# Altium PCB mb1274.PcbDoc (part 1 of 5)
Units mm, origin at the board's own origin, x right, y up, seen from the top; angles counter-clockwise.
Board outline 70 x 105 mm, 4 copper layers (Top Layer, Mid-Layer 1, Mid-Layer 2, Bottom Layer), stack 1.58 mm thick; 329 components, 271 nets, 1213 pads, 779 vias.
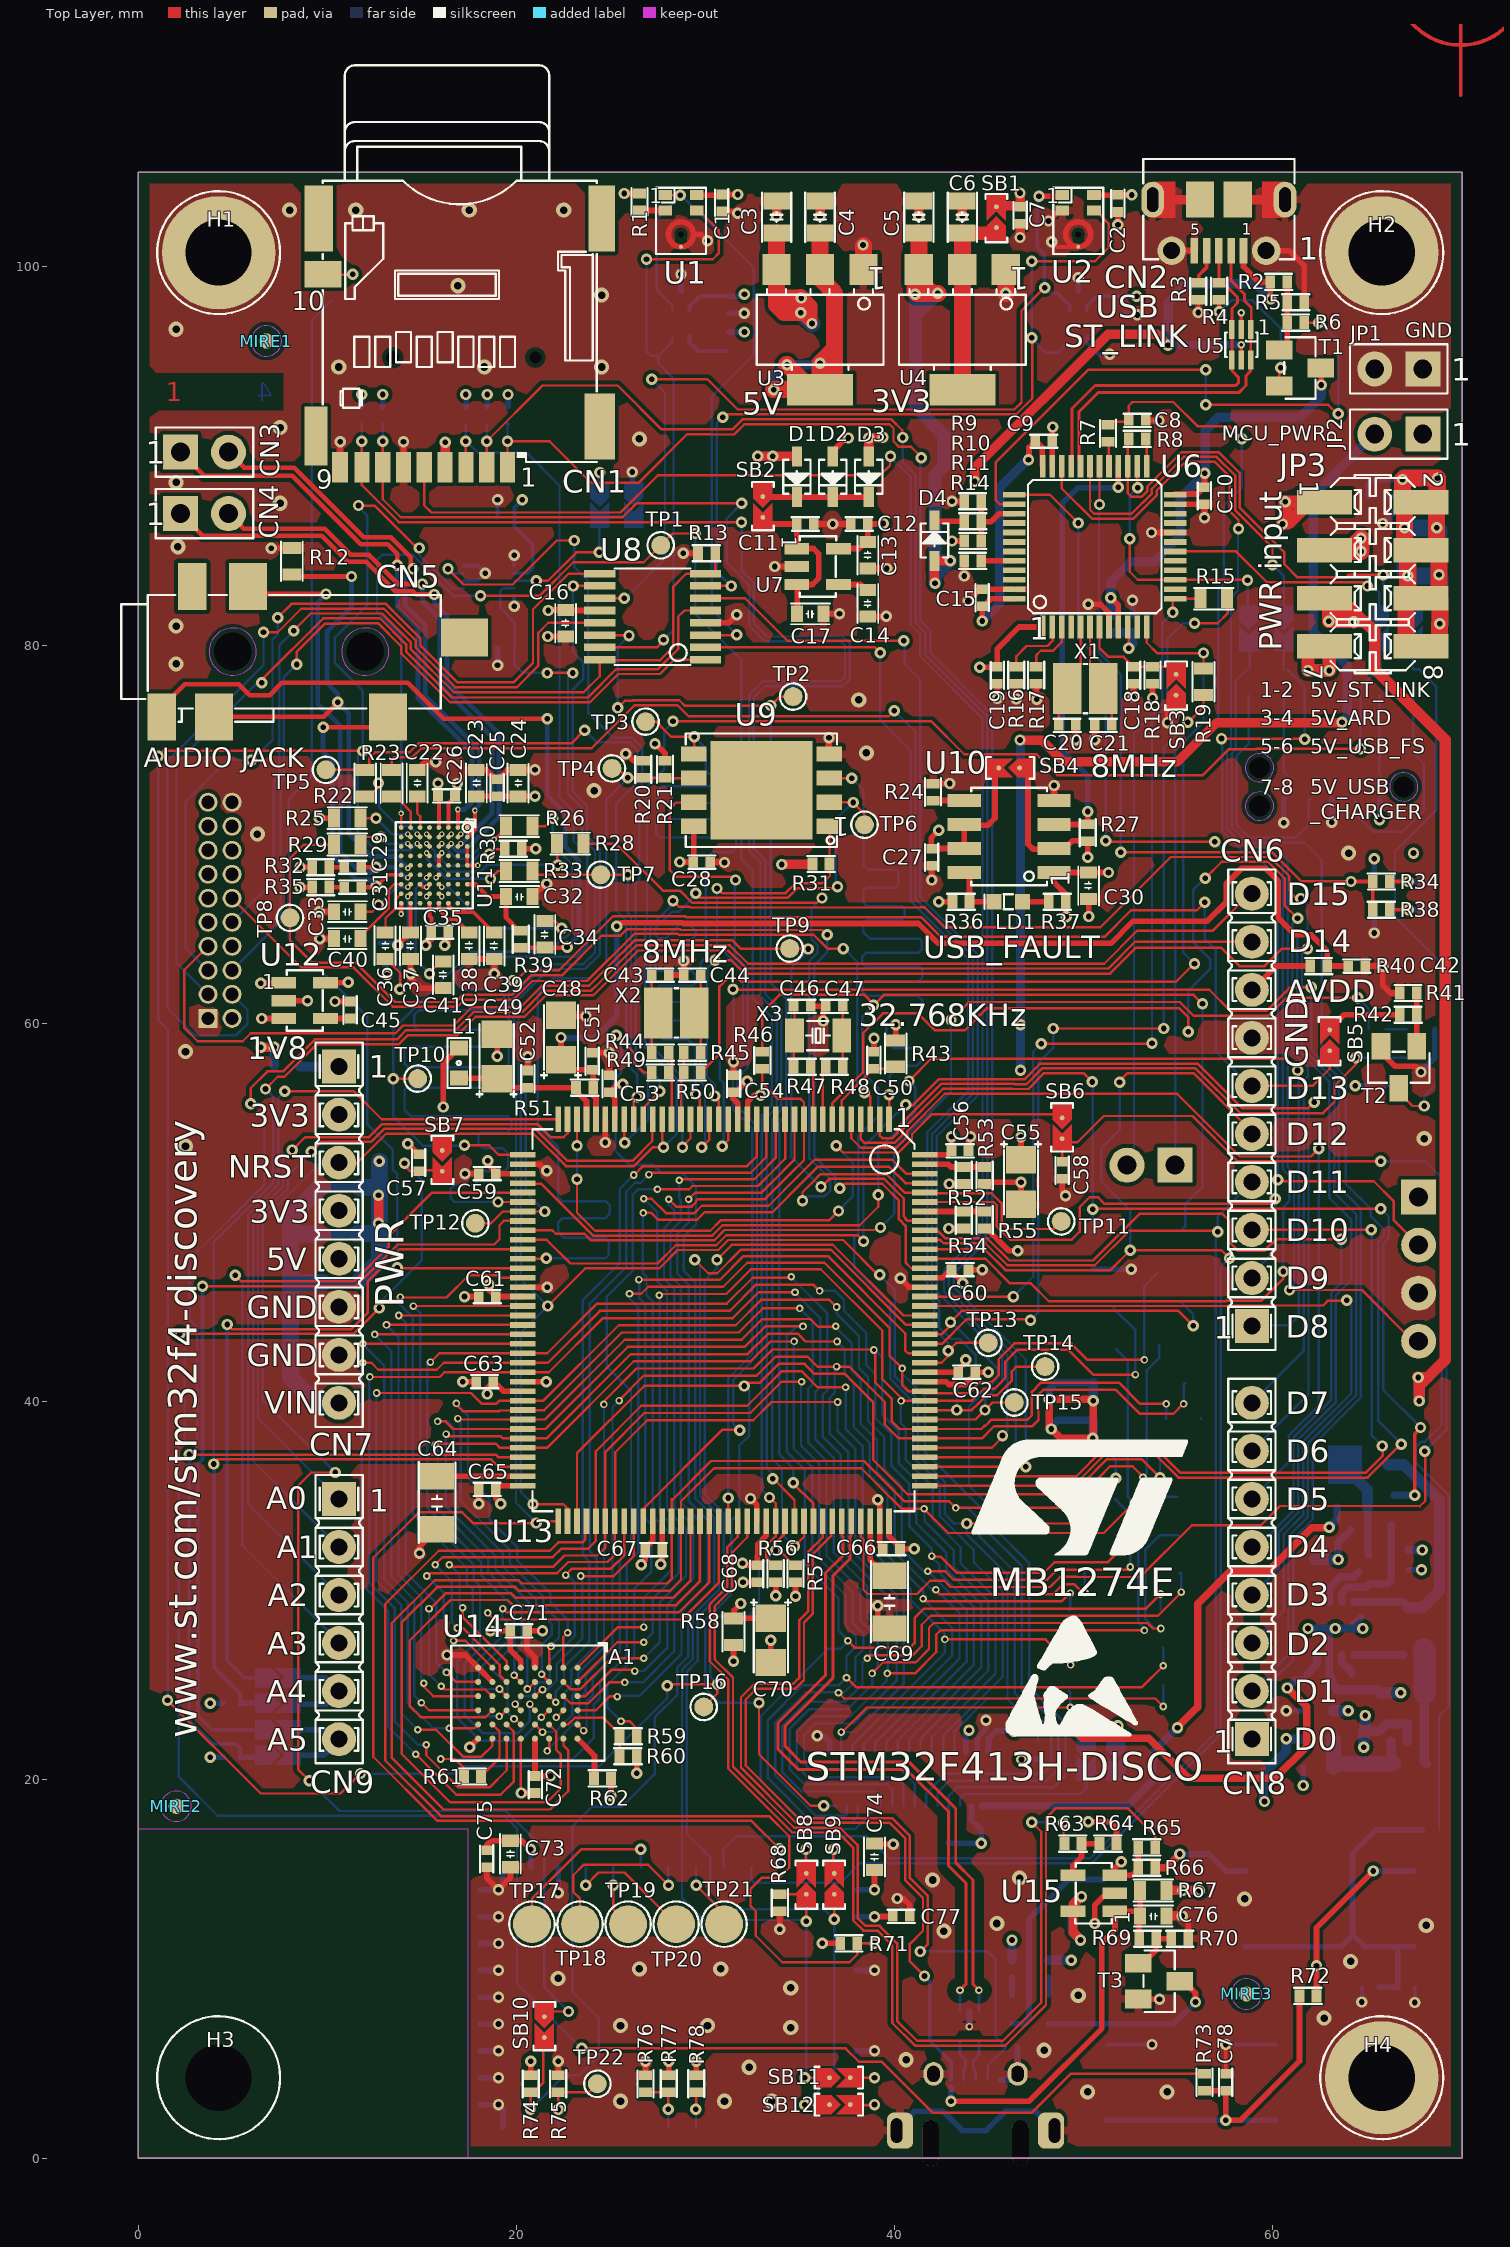
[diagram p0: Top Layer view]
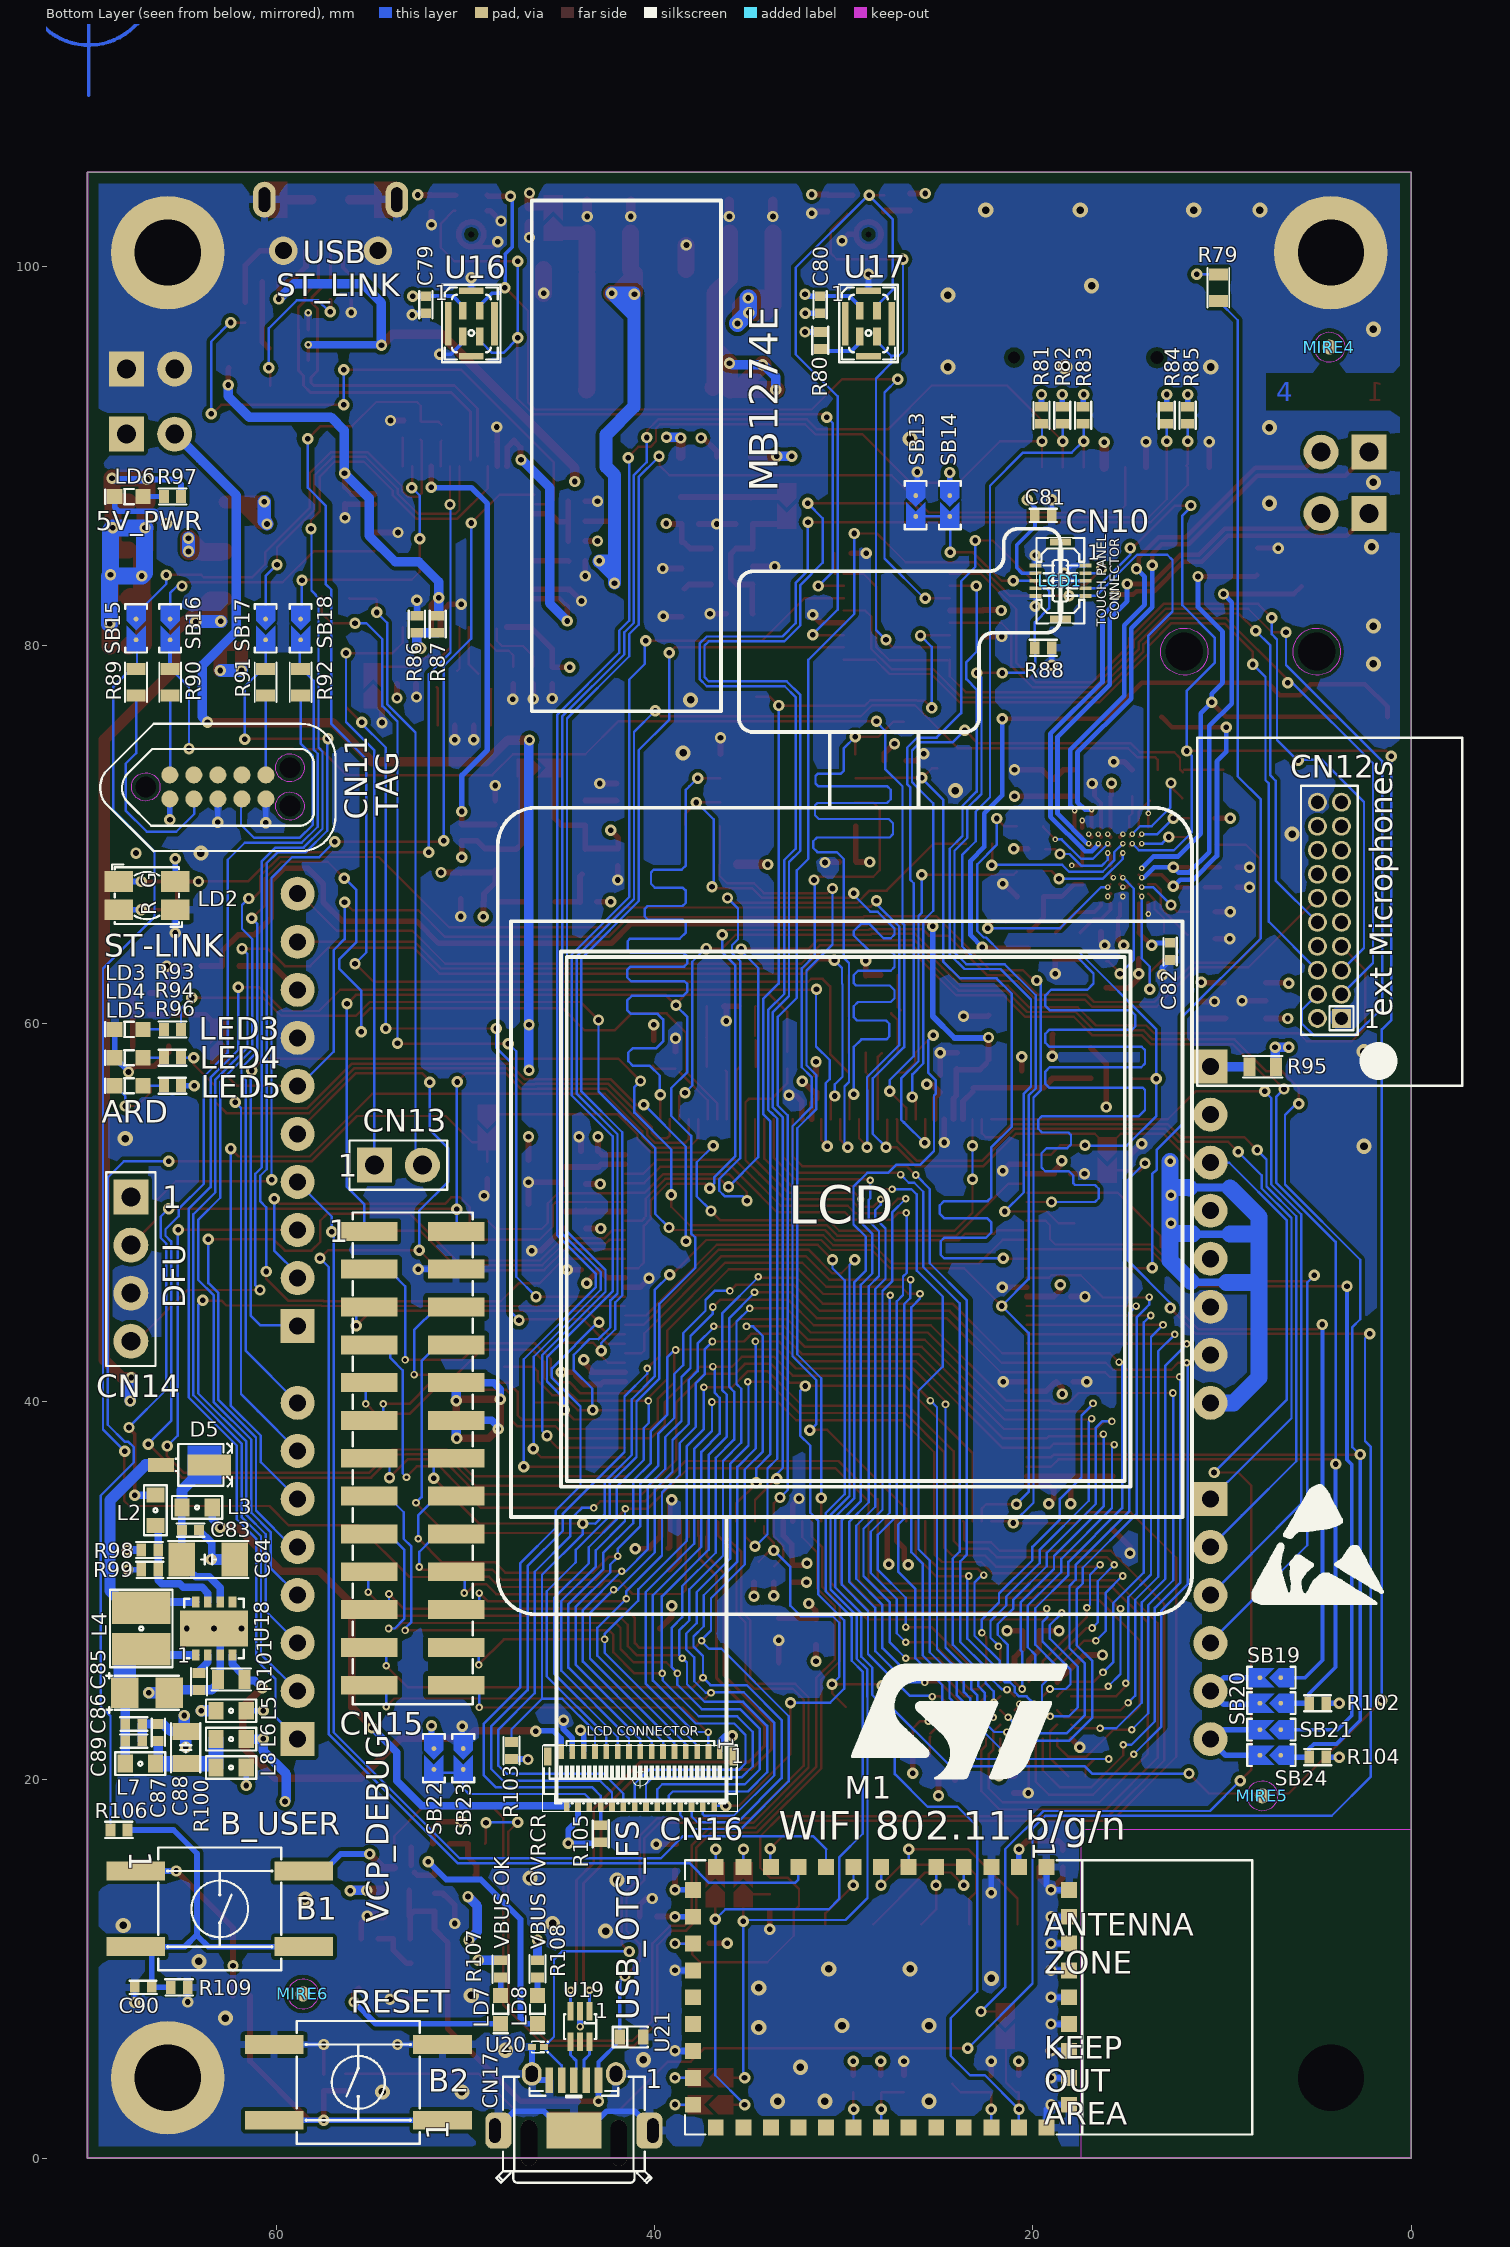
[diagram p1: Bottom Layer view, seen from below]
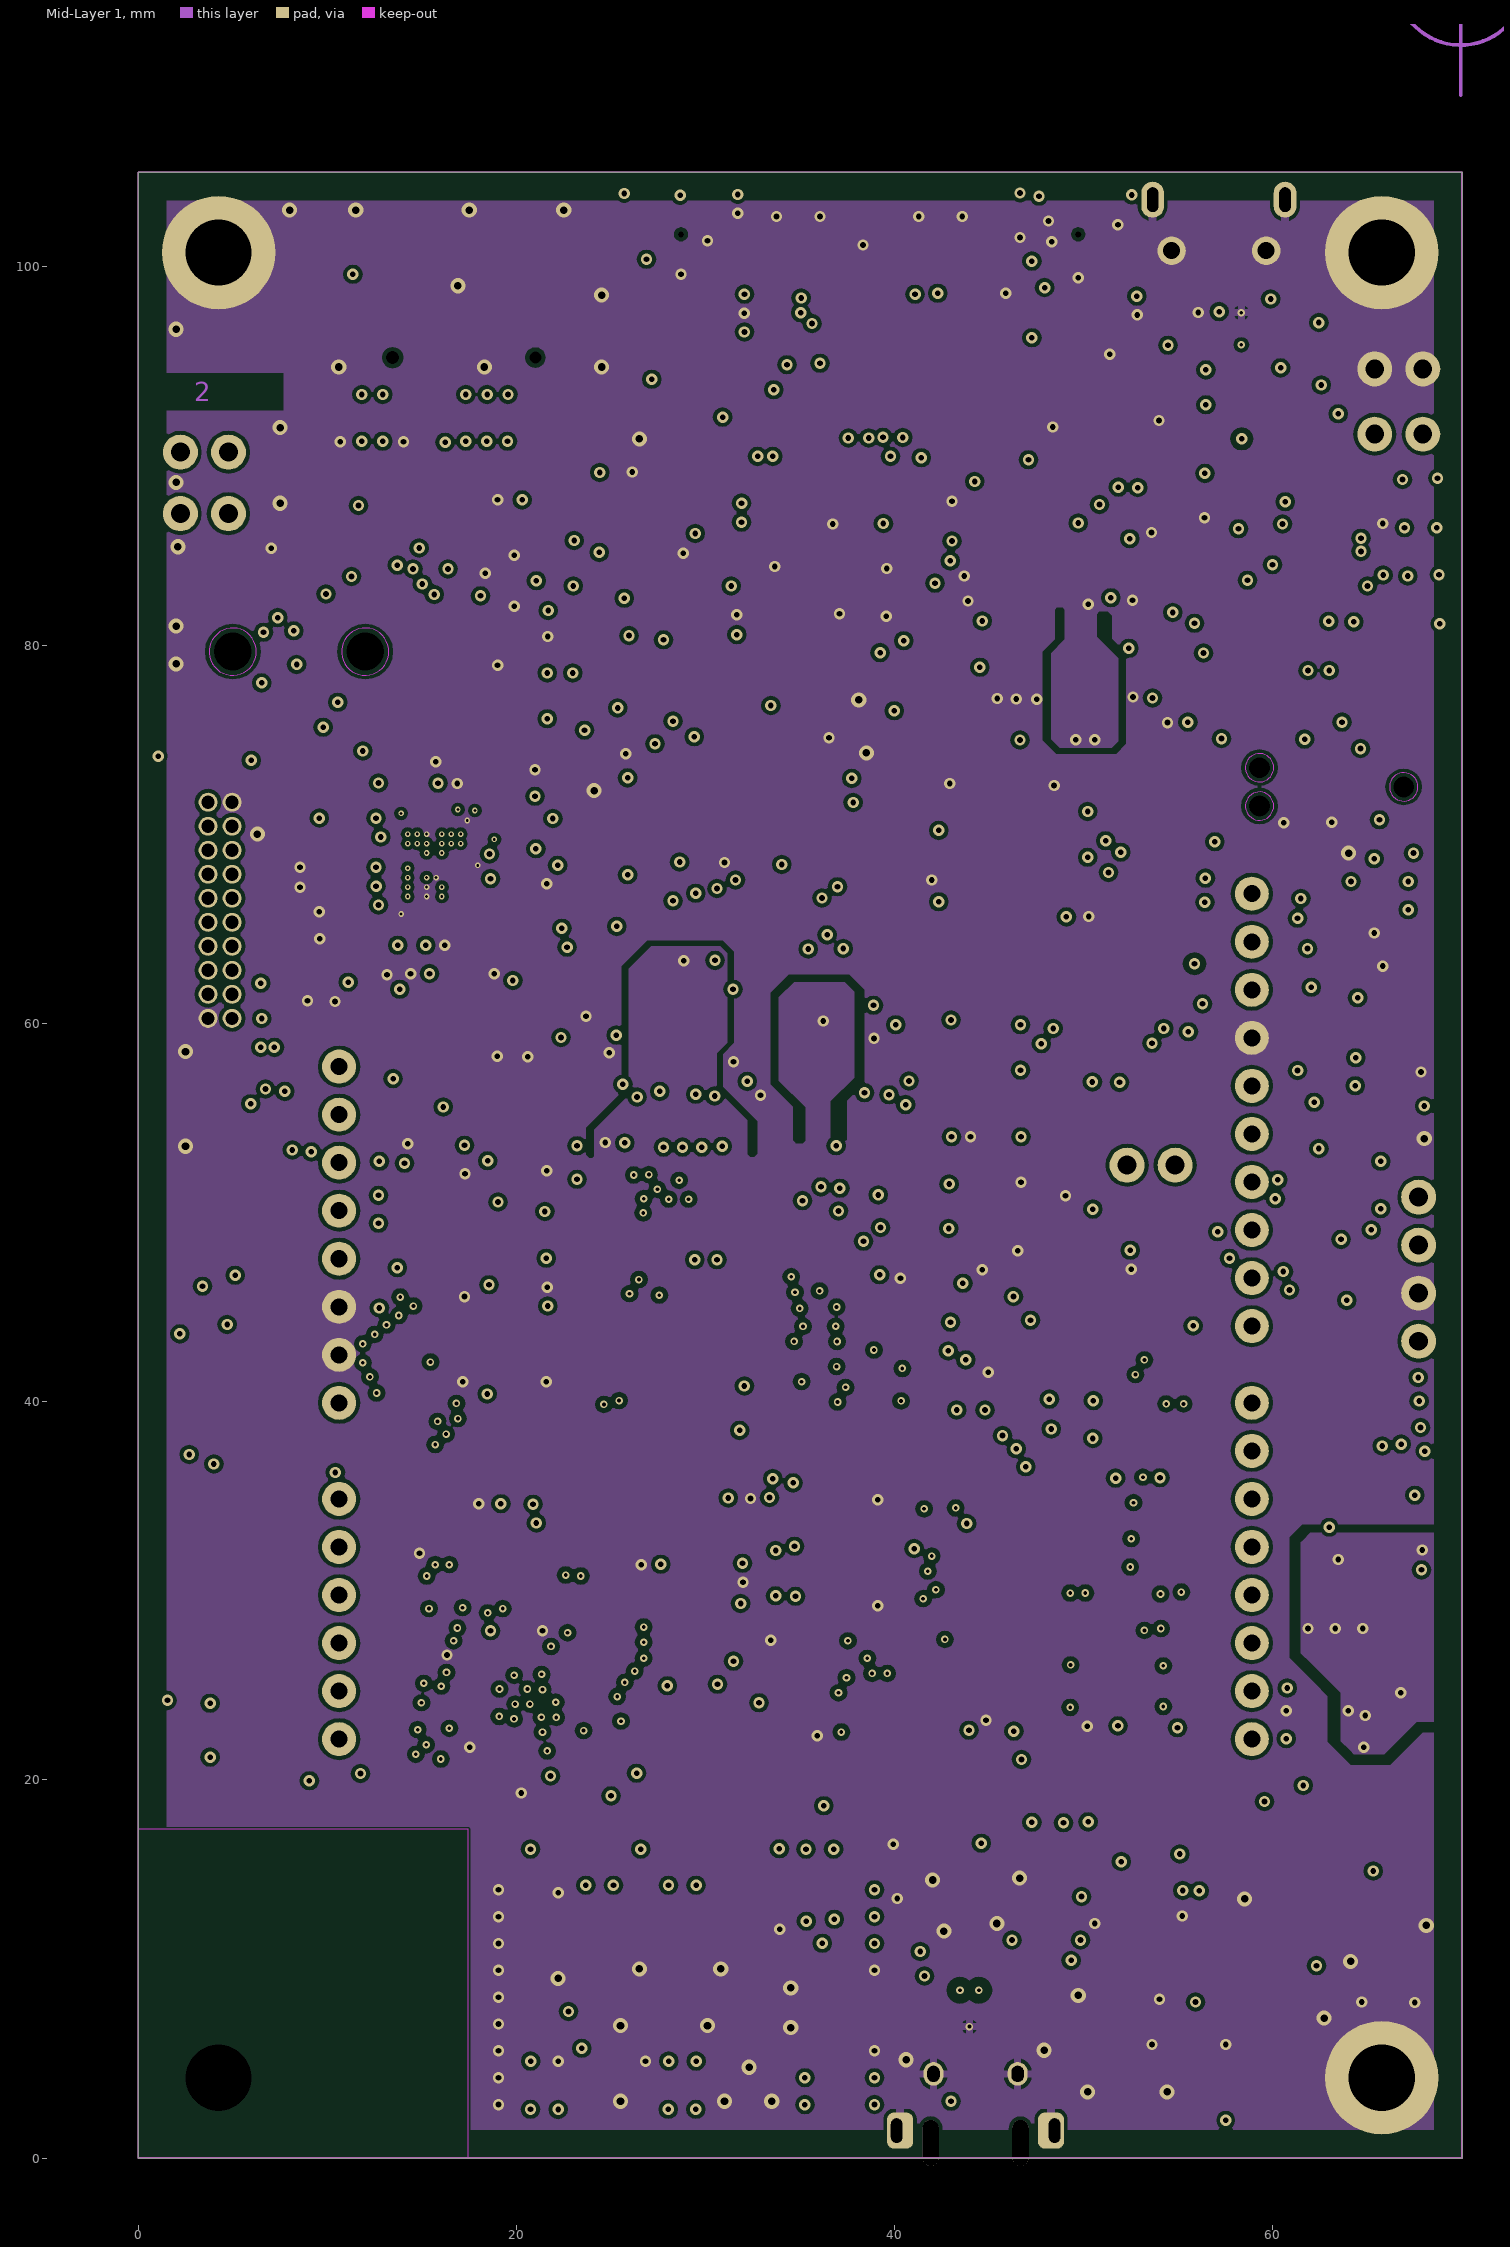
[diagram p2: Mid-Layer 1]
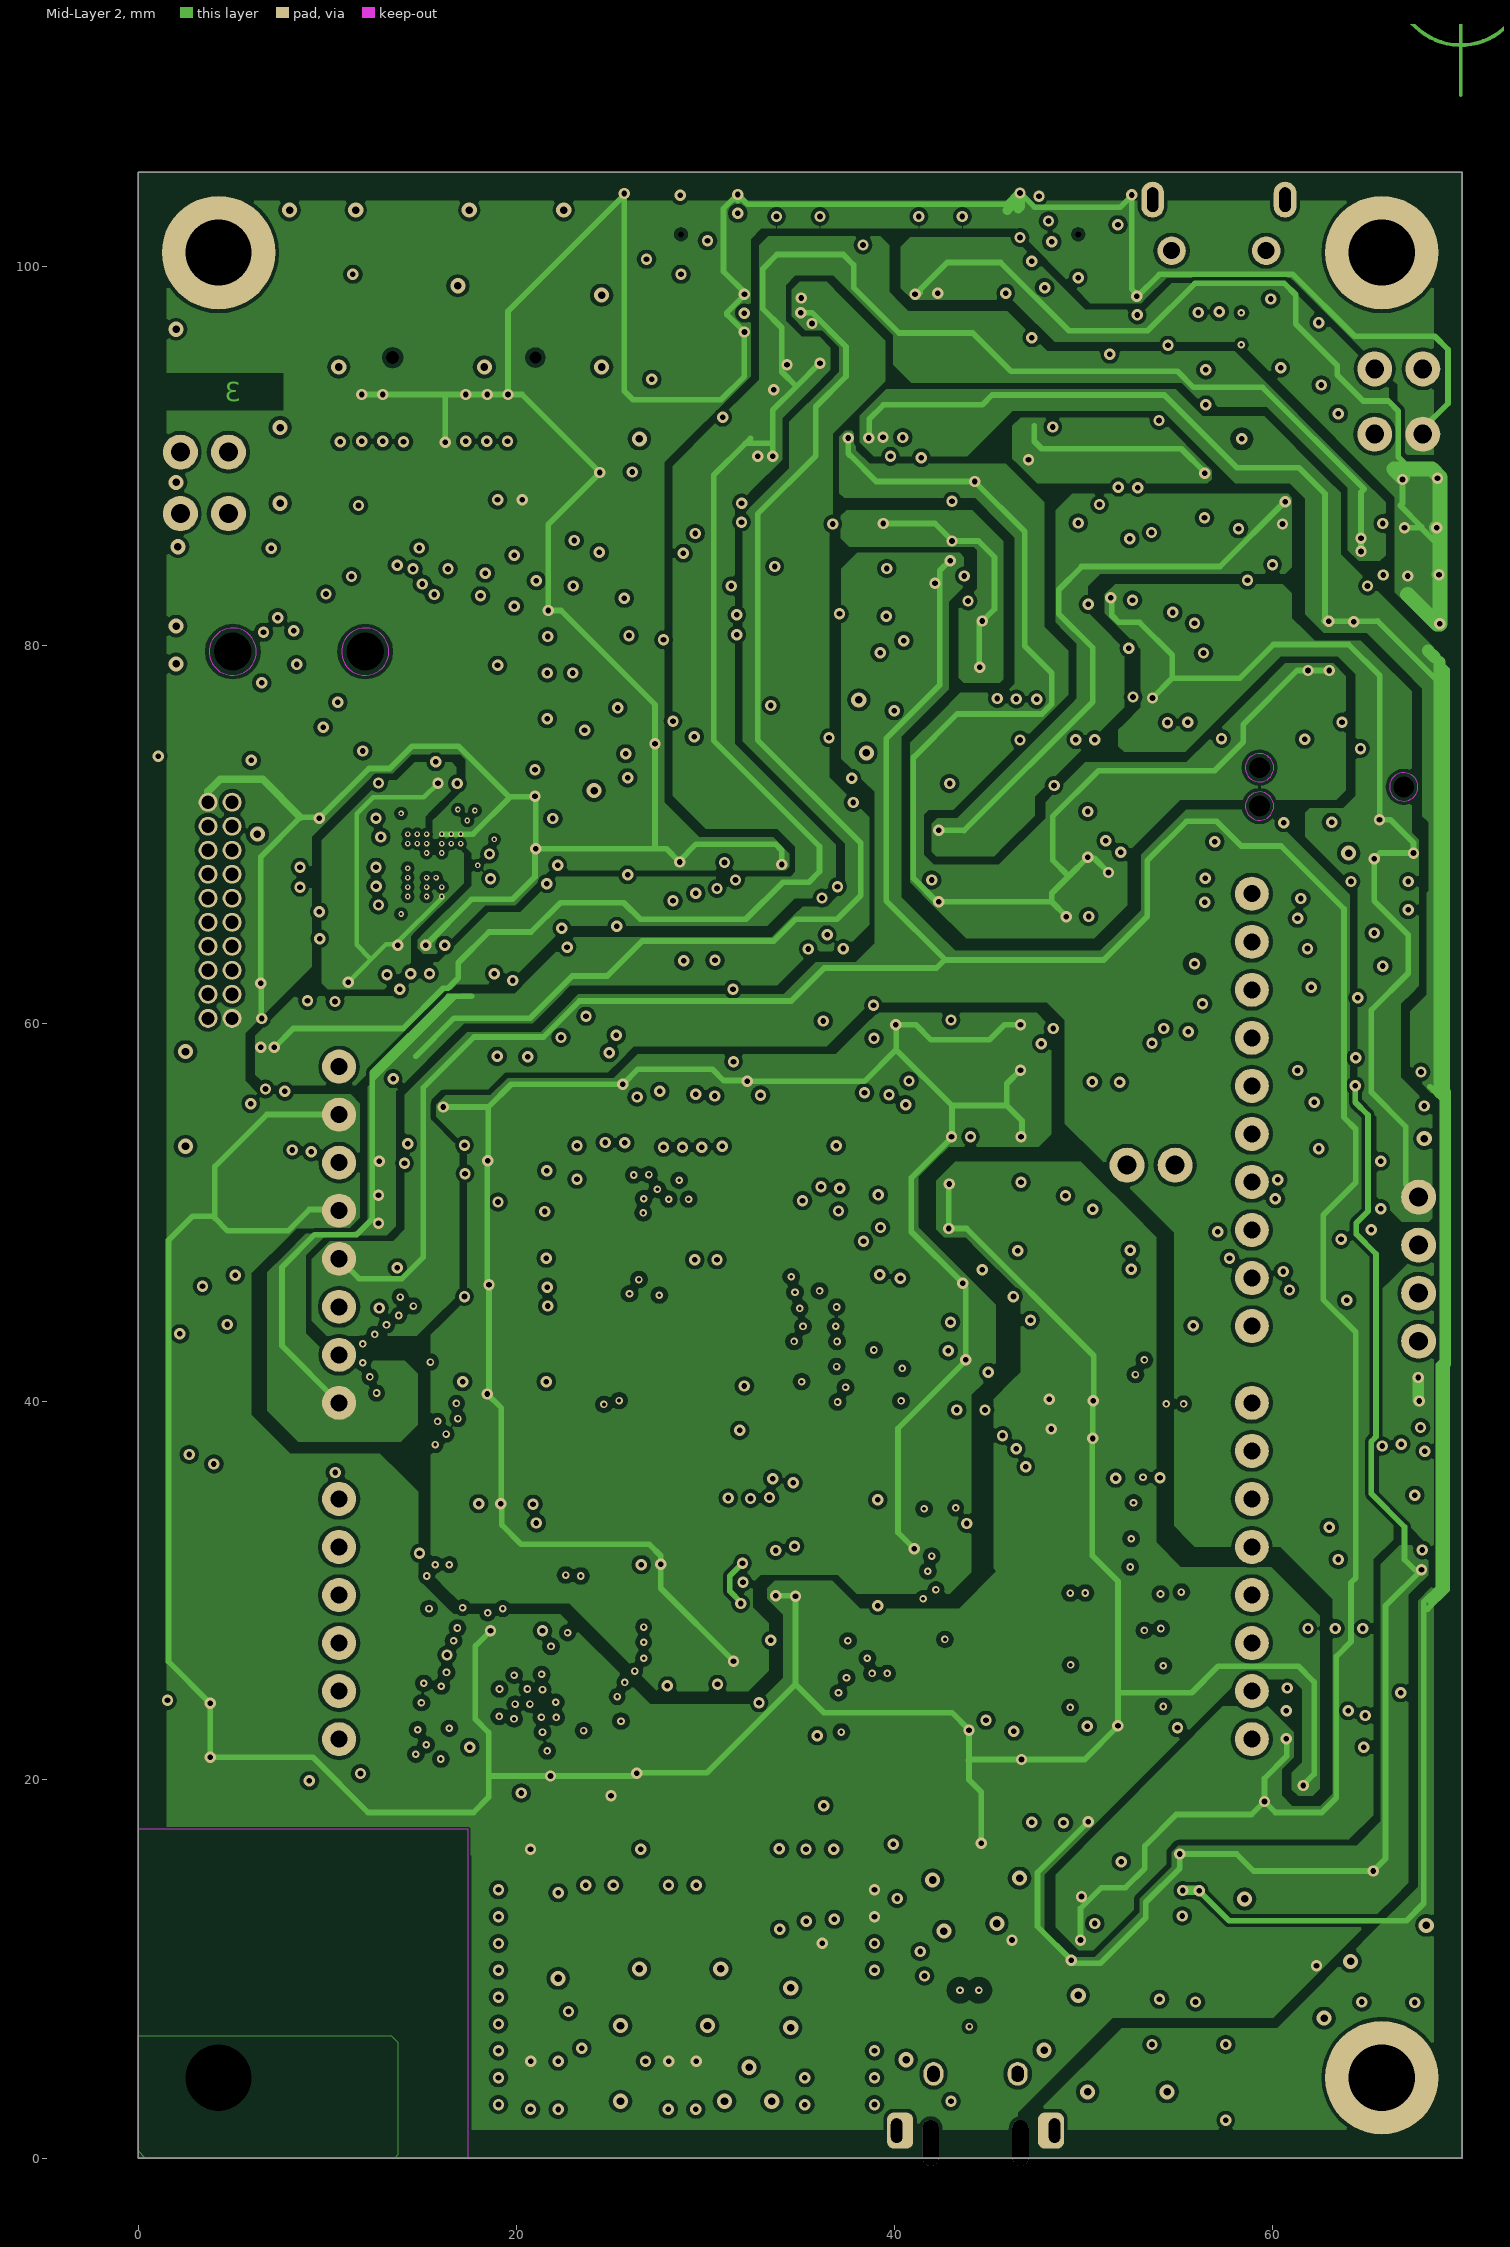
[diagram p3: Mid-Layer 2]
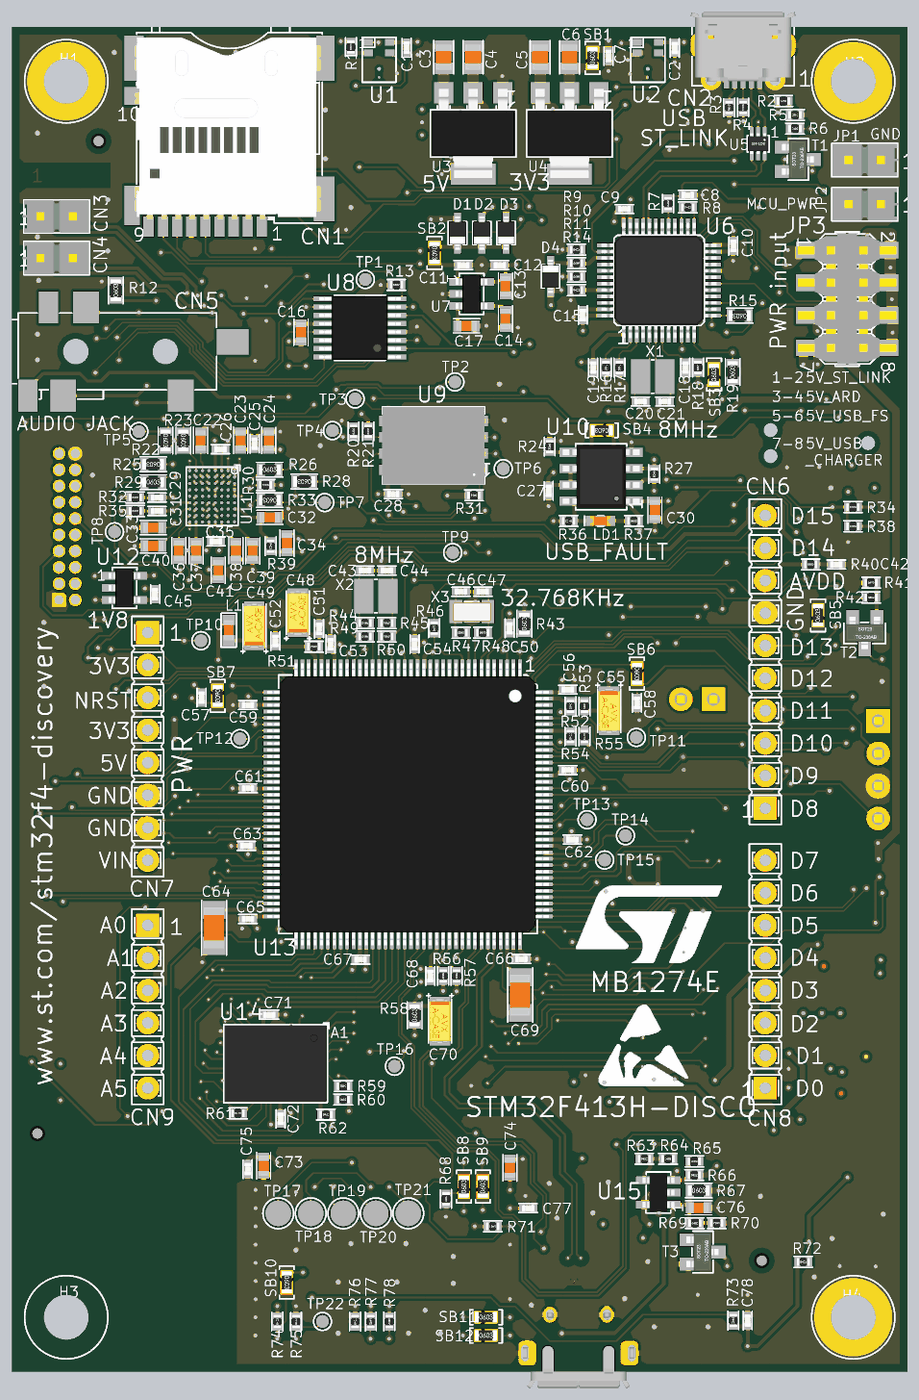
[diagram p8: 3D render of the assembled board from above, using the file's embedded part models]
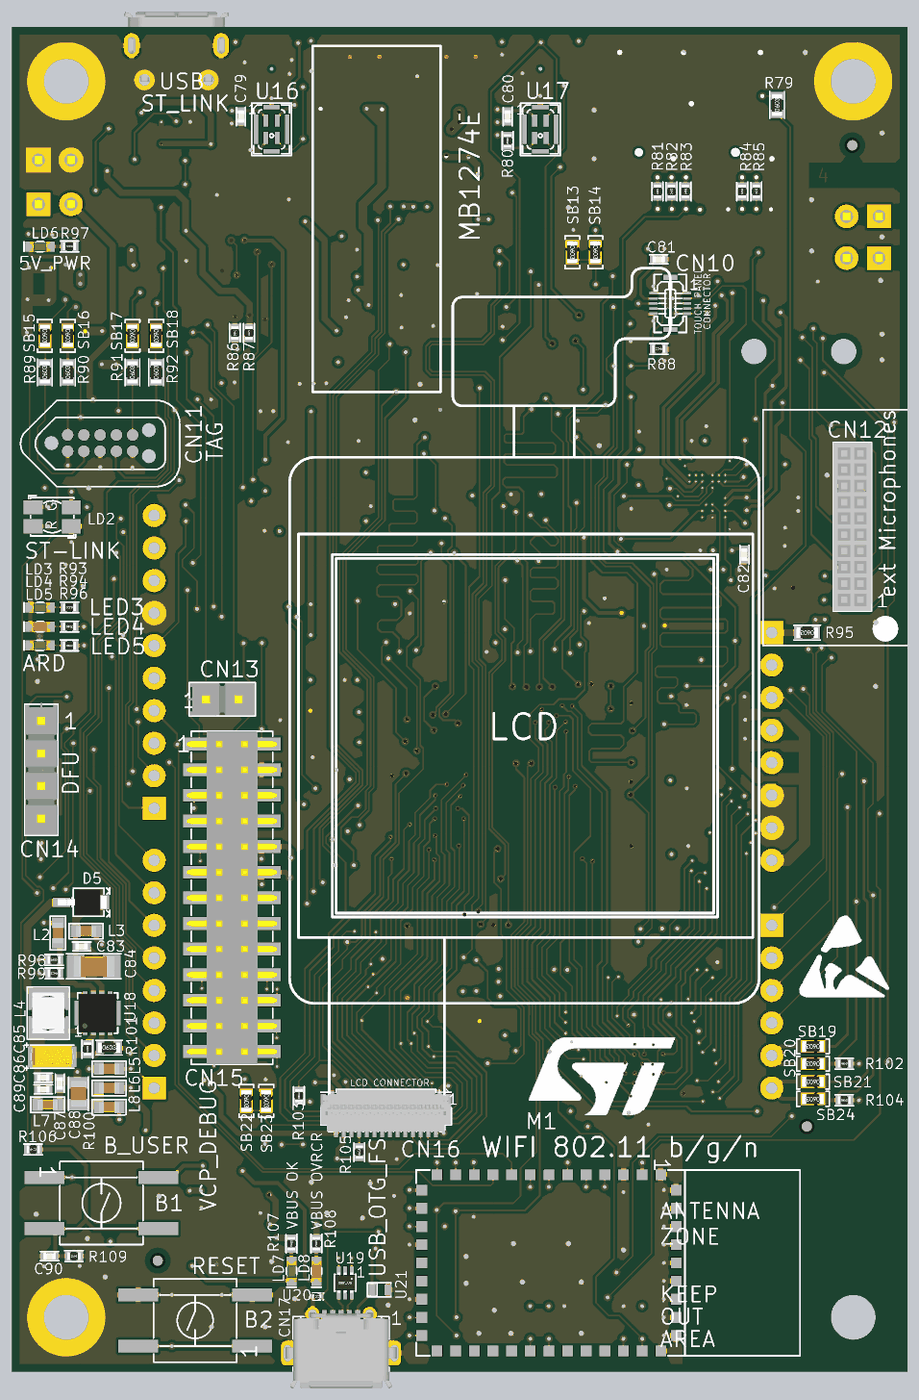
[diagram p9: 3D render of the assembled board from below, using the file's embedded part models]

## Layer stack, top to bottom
Top Solder: solder mask 0.01, Solder Resist, Dk 3.5
Top Layer: signal copper 0.035
Dielectric 1: dielectric 0.108, FR-4, Dk 4.8
Mid-Layer 1: signal copper 0.035
Dielectric2: dielectric 1.224, FR-4, Dk 4.8
Mid-Layer 2: signal copper 0.035
Dielectric3: dielectric 0.108, FR-4, Dk 4.8
Bottom Layer: signal copper 0.035
Bottom Solder: solder mask 0.01, Solder Resist, Dk 3.5

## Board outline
0,0 70,0 70,105 0,105

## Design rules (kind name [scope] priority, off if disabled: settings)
BoardOutlineClearance BoardOutlineClearance_L2 [OnLayer('Mid-Layer 1')] p1: gap=0.6 ignorepadtopadclearanceinfootprint=FALSE except(1.5: Poly-OutlineEdge Poly-CavityEdge Poly-CutoutEdge Poly-SplitBarrior Poly-SplitContinuation)
BoardOutlineClearance BoardOutlineClearance_L3 [OnLayer('Mid-Layer 2')] p2: gap=0.6 ignorepadtopadclearanceinfootprint=FALSE except(1.5: Poly-OutlineEdge Poly-CavityEdge Poly-CutoutEdge Poly-SplitBarrior Poly-SplitContinuation)
BoardOutlineClearance BoardOutlineClearance_L1 [OnLayer('Top Layer')] p3: gap=0.6 ignorepadtopadclearanceinfootprint=FALSE
BoardOutlineClearance BoardOutlineClearance_L4 [OnLayer('Bottom Layer')] p4: gap=0.6 ignorepadtopadclearanceinfootprint=FALSE
Clearance CLEAR_CLK [InNet('STLK_MCO')] p1: gap=0.127 ignorepadtopadclearanceinfootprint=FALSE except(0: Arc-Hole Track-Hole SMDPad-Hole THPad-Hole Via-Hole Fill-Hole Poly-Hole Region-Hole Text-Hole; 0.2: SMDPad-SMDPad SMDPad-THPad THPad-THPad Via-Via; 0.3: Arc-Fill Arc-Poly Track-Track Track-Fill Track-Poly SMDPad-Fill SMDPad-Poly THPad-Fill THPad-Poly Via-Fill Via-Poly Fill-Fill Fill-Poly Poly-Poly)
Clearance CLEAR_AUDIO [InNetClass('BGA_AUDIO')] p2: gap=0.127 ignorepadtopadclearanceinfootprint=FALSE except(0: Arc-Hole Track-Hole SMDPad-Hole THPad-Hole Via-Hole Fill-Hole Poly-Hole Region-Hole Text-Hole; 0.1: Arc-SMDPad SMDPad-Via; 0.2: Arc-Fill Arc-Poly Track-Fill Track-Poly SMDPad-SMDPad SMDPad-THPad SMDPad-Fill SMDPad-Poly THPad-THPad THPad-Fill THPad-Poly Via-Via Via-Fill Via-Poly Fill-Poly; 0.3: Fill-Fill Poly-Poly)
Clearance Clear_DiffP-90R_USB_STLK [InNetClass('DiffP-90R_USB_STLK')] p3: gap=0.127 ignorepadtopadclearanceinfootprint=FALSE except(0: Arc-Hole Track-Hole SMDPad-Hole THPad-Hole Via-Hole Fill-Hole Poly-Hole Region-Hole Text-Hole; 0.2: SMDPad-SMDPad SMDPad-THPad THPad-THPad Via-Via; 0.225: Track-Track; 0.5: Arc-Fill Arc-Poly Track-Fill Track-Poly SMDPad-Fill SMDPad-Poly THPad-Fill THPad-Poly Via-Fill Via-Poly Fill-Fill Fill-Poly Poly-Poly)
Clearance Clear_DiffP-90R_USB_OTG_FS [InNetClass('DiffP-90R_USB_OTG_FS')] p4: gap=0.127 ignorepadtopadclearanceinfootprint=FALSE except(0: Arc-Hole Track-Hole SMDPad-Hole THPad-Hole Via-Hole Fill-Hole Poly-Hole Region-Hole Text-Hole; 0.2: SMDPad-SMDPad SMDPad-THPad THPad-THPad Via-Via; 0.225: Track-Track; 0.5: Arc-Fill Arc-Poly Track-Fill Track-Poly SMDPad-Fill SMDPad-Poly THPad-Fill THPad-Poly Via-Fill Via-Poly Fill-Fill Fill-Poly Poly-Poly)
Clearance CLEAR_55R_LCD-PSRAM [InNetClass('LCD_PSRAM_D0-15_55R')] p5: gap=0.127 ignorepadtopadclearanceinfootprint=FALSE except(0: Arc-Hole Track-Hole SMDPad-Hole THPad-Hole Via-Hole Fill-Hole Poly-Hole Region-Hole Text-Hole; 0.2: SMDPad-SMDPad SMDPad-THPad THPad-THPad Via-Via; 0.22: Track-Track; 0.254: Arc-Fill Arc-Poly Track-Fill Track-Poly SMDPad-Fill SMDPad-Poly THPad-Fill THPad-Poly Via-Fill Via-Poly Fill-Poly; 0.3: Fill-Fill Poly-Poly)
Clearance CLEAR_55R_xPSRAMx [InNetClass('xPSRAMx_55R')] p6: gap=0.127 ignorepadtopadclearanceinfootprint=FALSE except(0: Arc-Hole Track-Hole SMDPad-Hole THPad-Hole Via-Hole Fill-Hole Poly-Hole Region-Hole Text-Hole; 0.2: SMDPad-SMDPad SMDPad-THPad THPad-THPad Via-Via; 0.22: Track-Track; 0.254: Arc-Fill Arc-Poly Track-Fill Track-Poly SMDPad-Fill SMDPad-Poly THPad-Fill THPad-Poly Via-Fill Via-Poly Fill-Poly; 0.3: Fill-Fill Poly-Poly)
Clearance [All] p7: gap=0.127 ignorepadtopadclearanceinfootprint=FALSE except(0: Arc-Hole Track-Hole SMDPad-Hole THPad-Hole Via-Hole Fill-Hole Poly-Hole Region-Hole Text-Hole; 0.1: SMDPad-Via; 0.12: Arc-SMDPad; 0.15: SMDPad-SMDPad; 0.2: Arc-Fill Arc-Poly Track-Fill Track-Poly SMDPad-THPad SMDPad-Fill SMDPad-Poly THPad-THPad THPad-Fill THPad-Poly Via-Via Via-Fill Via-Poly Fill-Poly; 0.3: Fill-Fill Poly-Poly)
ComponentClearance [All] p1: gap=0.025 collisioncheckmode=3 verticalgap=0 showdistances=TRUE
DiffPairsRouting DiffP-90R_USB_STLK [InDifferentialPairClass('DiffP-90R_USB_STLK')] p1: maxlimit=0.226 minlimit=0.226 mostfreqgap=0.226 toplayer_minwidth=0.155 toplayer_maxwidth=0.155 toplayer_prefwidth=0.155 midlayer1_minwidth=0.155 midlayer1_maxwidth=0.155 midlayer1_prefwidth=0.155 midlayer2_minwidth=0.155 midlayer2_maxwidth=0.155 midlayer2_prefwidth=0.155 bottomlayer_minwidth=0.155 bottomlayer_maxwidth=0.155 bottomlayer_prefwidth=0.155 maxuncoupledlength=12.7
DiffPairsRouting DiffP-90R_USB_OTG_FS [InDifferentialPairClass('DiffP-90R_USB_OTG_FS')] p2: maxlimit=0.226 minlimit=0.226 mostfreqgap=0.226 toplayer_minwidth=0.155 toplayer_maxwidth=0.155 toplayer_prefwidth=0.155 midlayer1_minwidth=0.155 midlayer1_maxwidth=0.155 midlayer1_prefwidth=0.155 midlayer2_minwidth=0.155 midlayer2_maxwidth=0.155 midlayer2_prefwidth=0.155 bottomlayer_minwidth=0.155 bottomlayer_maxwidth=0.155 bottomlayer_prefwidth=0.155 maxuncoupledlength=12.7
DiffPairsRouting [All] p3: maxlimit=0.254 minlimit=0.254 mostfreqgap=0.254 toplayer_minwidth=0.381 toplayer_maxwidth=0.381 toplayer_prefwidth=0.381 midlayer1_minwidth=0.381 midlayer1_maxwidth=0.381 midlayer1_prefwidth=0.381 midlayer2_minwidth=0.381 midlayer2_maxwidth=0.381 midlayer2_prefwidth=0.381 bottomlayer_minwidth=0.381 bottomlayer_maxwidth=0.381 bottomlayer_prefwidth=0.381 maxuncoupledlength=12.7
FanoutControl Fanout_BGA [IsBGA] p1: bgadir=Out bgaviamode=Closest fanoutstyle=Auto fanoutdirection=Alternating viagrid=0.025 // Fanout_BGA (Default Rule)
FanoutControl Fanout_LCC [IsLCC] p2: bgadir=Out bgaviamode=Closest fanoutstyle=Auto fanoutdirection=Alternating viagrid=0.025 // Fanout_LCC (Default Rule)
FanoutControl Fanout_SOIC [IsSOIC] p3: bgadir=Out bgaviamode=Closest fanoutstyle=Auto fanoutdirection=Alternating viagrid=0.025 // Fanout_SOIC (Default Rule)
FanoutControl Fanout_Small [(CompPinCount < 5)] p4: bgadir=Out bgaviamode=Closest fanoutstyle=Auto fanoutdirection=OutThenIn viagrid=0.025 // Fanout_Small (Default Rule)
FanoutControl Fanout_Default [All] p5: bgadir=Out bgaviamode=Closest fanoutstyle=Auto fanoutdirection=Alternating viagrid=0.025 // Fanout_Default (Default Rule)
Height [All] p1: minheight=0 maxheight=100 prefheight=0.5
HoleSize [All] p1: absolutevalues=TRUE maxlimit=10 minlimit=0.15 maxpercent=80.000 minpercent=20.000
HoleToHoleClearance HoleToHoleClear_AUDIO-BGA [IsVia] p1: gap=0.35 allowstackedmicrovias=TRUE
HoleToHoleClearance [All] p2: gap=0.39 allowstackedmicrovias=TRUE
MatchedLengths SD-CARD [InNetClass('SD-CARD')] p1: tolerance=5 checknetsindiffpair=FALSE checkdiffpairvsdiffpair=TRUE checkxsignals=TRUE checkothers=TRUE
MatchedLengths xPSRAMx_55R [InNetClass('xPSRAMx_55R')] p2: tolerance=100 checknetsindiffpair=FALSE checkdiffpairvsdiffpair=TRUE checkxsignals=TRUE checkothers=TRUE
MatchedLengths QSPI [InNetClass('QSPI')] p3: tolerance=5 checknetsindiffpair=FALSE checkdiffpairvsdiffpair=TRUE checkxsignals=TRUE checkothers=TRUE
MatchedLengths LCD_PSRAM_D0-15_55R [InNetClass('LCD_PSRAM_D0-15_55R')] p4: tolerance=100 checknetsindiffpair=FALSE checkdiffpairvsdiffpair=TRUE checkxsignals=TRUE checkothers=TRUE
MinimumSolderMaskSliver [All] p1: minsoldermaskwidth=0
PlaneClearance [All] p1: clearance=0.6
PlaneConnect [All] p1: planeconnectstyle=Relief reliefexpansion=0.5 reliefentries=4 reliefconductorwidth=0.3 reliefairgap=0.2
PolygonConnect PolygonConnect_Maillage [(ObjectKind = 'Via') And (AsMM(ViaDiameter) = 0.8) And (AsMM(HoleDiameter) = 0.4)] p1: connectstyle=Direct reliefconductorwidth=0.254 reliefentries=4 polygonreliefangle="90 Angle" airgapwidth=0.254
PolygonConnect PolygonConnect_Via-015030-GND-direct [(ObjectKind = 'Via') And (Net = 'GND') And (AsMM(ViaDiameter) = 0.3) And (AsMM(HoleDiameter) = 0.15)] p2: connectstyle=Direct reliefconductorwidth=0.254 reliefentries=4 polygonreliefangle="90 Angle" airgapwidth=0.254
PolygonConnect PolygonConnect_PTH-07-direct [(ObjectKind = 'Pad') And (AsMM(HoleDiameter) = 0.7)] p3: connectstyle=Direct reliefconductorwidth=0.254 reliefentries=4 polygonreliefangle="90 Angle" airgapwidth=0.254
PolygonConnect PolygonConnect_PTH-1-direct [(AsMM(HoleDiameter) = 1)] p4: connectstyle=Direct reliefconductorwidth=0.254 reliefentries=4 polygonreliefangle="90 Angle" airgapwidth=0.254
PolygonConnect PolygonConnect_PTH-09-direct [(AsMM(HoleDiameter) = 0.9)] p5: connectstyle=Direct reliefconductorwidth=0.254 reliefentries=4 polygonreliefangle="90 Angle" airgapwidth=0.254
PolygonConnect PolygonConnect_PTH-GND-direct [(ObjectKind = 'Pad') And (Net = 'GND') And (AsMM(HoleDiameter) = 3.5)] p6: connectstyle=Direct reliefconductorwidth=0.254 reliefentries=4 polygonreliefangle="90 Angle" airgapwidth=0.254
PolygonConnect PolygonConnect_Via-GND-direct [(ObjectKind = 'Via') And (Net = 'GND') And (AsMM(ViaDiameter) = 0.6) And (AsMM(HoleDiameter) = 0.3)] p7: connectstyle=Direct reliefconductorwidth=0.254 reliefentries=4 polygonreliefangle="90 Angle" airgapwidth=0.254
PolygonConnect Polygon_GND [InNet('GND')] p8: connectstyle=Relief reliefconductorwidth=0.4 reliefentries=4 polygonreliefangle="90 Angle" airgapwidth=0.2
PolygonConnect [All] p9: connectstyle=Direct reliefconductorwidth=0.3 reliefentries=4 polygonreliefangle="90 Angle" airgapwidth=0.3
RoutingVias VIA_ALIMS [InNetClass('ALIMS')] p1: holewidth=0.3 width=0.6 viastyle="Through Hole" minholewidth=0.15 minwidth=0.3 maxholewidth=0.3 maxwidth=0.6
RoutingVias VIA_GND [InNet('GND')] p2: holewidth=0.3 width=0.6 viastyle="Through Hole" minholewidth=0.15 minwidth=0.3 maxholewidth=0.3 maxwidth=0.6
RoutingVias VIA_AUDIO_015-030 [InNetClass('BGA_AUDIO')] p3: holewidth=0.15 width=0.3 viastyle="Through Hole" minholewidth=0.15 minwidth=0.3 maxholewidth=0.3 maxwidth=0.6
RoutingVias VIA_55R_xPSRAMx [InNetClass('xPSRAMx_55R')] p4: holewidth=0.2 width=0.4 viastyle="Through Hole" minholewidth=0.2 minwidth=0.4 maxholewidth=0.2 maxwidth=0.4
RoutingVias VIA_USB-STLK [InNetClass('DiffP-90R_USB_STLK')] p5: holewidth=0.2 width=0.4 viastyle="Through Hole" minholewidth=0.2 minwidth=0.4 maxholewidth=0.2 maxwidth=0.4
RoutingVias VIA_USB-OTG [InNetClass('DiffP-90R_USB_OTG_FS')] p6: holewidth=0.2 width=0.4 viastyle="Through Hole" minholewidth=0.2 minwidth=0.4 maxholewidth=0.2 maxwidth=0.4
RoutingVias VIA_55R_LCD-PSRAM [InNetClass('LCD_PSRAM_D0-15_55R')] p7: holewidth=0.2 width=0.4 viastyle="Through Hole" minholewidth=0.2 minwidth=0.4 maxholewidth=0.2 maxwidth=0.4
RoutingVias [All] p8: holewidth=0.3 width=0.6 viastyle="Through Hole" minholewidth=0.3 minwidth=0.6 maxholewidth=0.3 maxwidth=0.6
SilkToSilkClearance [All] p1: silktosilkclearance=0
SilkToSolderMaskClearance [IsPad] p1: minsilkscreentomaskgap=0 clearancetoexposedcopper=TRUE
SolderMaskExpansion [All] p1: expansion=0.05
Width WIDTH_ALIMS [InNetClass('ALIMS')] p1: maxlimit=1 minlimit=0.2 preferedwidth=0.3
Width WIDTH_55R_LCD-PSRAM [InNetClass('LCD_PSRAM_D0-15_55R')] p2: maxlimit=0.127 minlimit=0.127 preferedwidth=0.127
Width WIDTH_55R_xPSRAMx [InNetClass('xPSRAMx_55R')] p3: maxlimit=0.127 minlimit=0.127 preferedwidth=0.127
Width WIDTH_GND [InNetClass('GND')] p4: maxlimit=5 minlimit=0.1 preferedwidth=0.3
Width [All] p5: maxlimit=10 minlimit=0.1 preferedwidth=0.127
15 further rules are at their usual default settings.

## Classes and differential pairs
net class BGA_AUDIO: 1V8 HP_OUT_L HP_OUT_R I2CFMP1_SCL I2CFMP1_SDA NetC22_2 NetC32_2 NetC34_2 NetC36_1 NetC36_2 NetC38_2 NetC39_2 NetC40_1 NetC41_2 NetC43_1 NetCN3_1 NetCN3_2 NetCN4_1 NetCN4_2 NetCN5_3 NetR22_2 NetR23_2 NetR25_1 NetR26_1 NetR28_2 NetR29_2 NetR30_2 NetR61_2
net class LCD_PSRAM_D0-15_55R: LCD-PSRAM_D0 LCD-PSRAM_D1 LCD-PSRAM_D2 LCD-PSRAM_D3 LCD-PSRAM_D4 LCD-PSRAM_D5 LCD-PSRAM_D6 LCD-PSRAM_D7 LCD-PSRAM_D8 LCD-PSRAM_D9 LCD-PSRAM_D10 LCD-PSRAM_D11 LCD-PSRAM_D12 LCD-PSRAM_D13 LCD-PSRAM_D14 LCD-PSRAM_D15
differential pair class DiffP-90R_USB_OTG_FS: DiffP-90R_USB_OTG_FS
differential pair class DiffP-90R_USB_STLK: DiffP-90R_USB_STLK
net class DiffP-90R_USB_STLK: USB_STLK_N USB_STLK_P
net class DiffP-90R_USB_OTG_FS: USB_OTG_FS_N USB_OTG_FS_P
net class xPSRAMx_55R: LCD-PSRAM_NOE LCD-PSRAM_NWE PSRAM_A0 PSRAM_A1 PSRAM_A2 PSRAM_A3 PSRAM_A4 PSRAM_A5 PSRAM_A6 PSRAM_A7 PSRAM_A8 PSRAM_A9 PSRAM_A10 PSRAM_A11 PSRAM_A12 PSRAM_A13 PSRAM_A14 PSRAM_A15 PSRAM_A16 PSRAM_A17 PSRAM_NBL0 PSRAM_NBL1 PSRAM_NE1
net class QSPI: QSPI_BK1_IO0 QSPI_BK1_IO1 QSPI_BK1_IO2 QSPI_BK1_IO3 QSPI_BK1_NCS QSPI_CLK
net class ALIMS: 1V8 3V3 3V3_ST_LINK 5V 5V_ARD 5V_ST_LINK 5V_USB_CHARGER 5V_USB_FS LDO_3V3 PWR_ENN PWR_EXT VBUS_OVRCR VDD_MCU VDD_USB33 VDDA VIN VREF+
net class SD-CARD: SD_CLK SD_CMD SD_D0 SD_D1 SD_D2 SD_D3
differential pair DiffP-90R_USB_OTG_FS: +USB_OTG_FS_P -USB_OTG_FS_N
differential pair DiffP-90R_USB_STLK: +USB_STLK_P -USB_STLK_N

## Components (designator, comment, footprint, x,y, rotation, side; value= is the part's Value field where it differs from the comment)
B1 "B1" SWI_C&K_KSC721GLFS_BLUE 63,13.175 r180 bottom
B2 "B2" SWI_C&K_KSC321GLFS_BLACK 55.675,4 r0 bottom
C1 ".Designator" C0402 30.85,103.375 r90 top
C2 ".Designator" C0402 51.8,103.35 r90 top
C3 ".Designator" C0805 33.75,102.625 r270 top
C4 ".Designator" C0805 36.05,102.625 r270 top
C5 ".Designator" C0805 41.275,102.625 r270 top
C6 ".Designator" C0805 43.575,102.625 r270 top
C7 ".Designator" C0402 46.625,102.725 r90 top
C8 ".Designator" C0402 52.825,91.875 r180 top
C9 ".Designator" C0402 47.875,90.775 r180 top
C10 ".Designator" C0402 56.375,87.9 r90 top
C11 ".Designator" C0402 35.275,86.4 r180 top
C12 ".Designator" C0402 38.125,86.4 r0 top
C13 ".Designator" C0603 38.575,84.75 r90 top
C14 ".Designator" C0603 38.575,82.2 r90 top
C15 ".Designator" C0402 44.625,82.5 r270 top
C16 ".Designator" C0603 22.6,81.15 r90 top
C17 ".Designator" C0603 35.525,81.65 r180 top
C18 ".Designator" C0402 52.625,78.4 r90 top
C19 ".Designator" C0402 45.425,78.4 r90 top
C20 ".Designator" C0402 49.125,75.75 r0 top
C21 ".Designator" C0402 51.025,75.75 r180 top
C22 ".Designator" C0603 14.75,72.7 r270 top
C23 ".Designator" C0603 17.875,72.7 r270 top
C24 ".Designator" C0603 20.075,72.7 r270 top
C25 ".Designator" C0402 18.975,72.45 r270 top
C26 ".Designator" C0402 16.3,72.025 r180 top
C27 ".Designator" C0402 41.95,68.775 r90 top
C28 ".Designator" C0402 29.8,68.525 r180 top
C29 ".Designator" C0402 11.35,68.25 r0 top
C30 ".Designator" C0603 50.25,67.275 r90 top
C31 ".Designator" C0402 11.35,67.2 r0 top
C32 ".Designator" C0603 20.15,66.7 r180 top
C33 ".Designator" C0603 11.05,65.9 r180 top
C34 ".Designator" C0603 21.5,64.7 r90 top
C35 ".Designator" C0402 15.95,64.825 r180 top
C36 ".Designator" C0603 13.05,64.1 r270 top
C37 ".Designator" C0603 14.4,64.1 r90 top
C38 ".Designator" C0603 17.5,64.1 r90 top
C39 ".Designator" C0603 18.825,64.1 r90 top
C40 ".Designator" C0603 11.05,64.475 r180 top
C41 ".Designator" C0603 16.125,62.575 r90 top
C42 ".Designator" C0402 64.425,63.025 r180 top
C43 ".Designator" C0402 27.6,62.55 r0 top
C44 ".Designator" C0402 29.3,62.55 r180 top
C45 ".Designator" C0402 11.2,60.7 r270 top
C46 ".Designator" C0402 35.1,60.9 r0 top
C47 ".Designator" C0402 36.8,60.9 r180 top
C48 ".Designator" CPOL_TAJ-A_1206_H180 22.35,59.25 r90 top
C49 ".Designator" CPOL_TAJ-A_1206_H180 18.95,58.25 r90 top
C50 ".Designator" C0402 38.9,58.05 r270 top
C51 ".Designator" C0402 24,58 r270 top
C52 ".Designator" C0402 20.6,57.05 r270 top
C53 ".Designator" C0402 24.9,56.8 r270 top
C54 ".Designator" C0402 31.475,56.8 r270 top
C55 ".Designator" CPOL_TAJ-A_1206_H180 46.675,51.6 r270 top
C56 ".Designator" C0402 43.45,53.25 r180 top
C57 ".Designator" C0402 14.825,52.625 r270 top
C58 ".Designator" C0402 48.85,52.225 r90 top
C59 ".Designator" C0402 18.45,52.05 r0 top
C60 ".Designator" C0402 43.45,46.975 r180 top
C61 ".Designator" C0402 18.45,45.55 r0 top
C62 ".Designator" C0402 43.8,41.55 r180 top
C63 ".Designator" C0402 18.325,41.05 r0 top
C64 ".Designator" C1206 15.8,34.65 r90 top
C65 ".Designator" C0402 18.45,35.35 r0 top
C66 ".Designator" C0402 39.825,32.225 r0 top
C67 ".Designator" C0402 27.25,32.175 r0 top
C68 ".Designator" C0402 32.7,30.9 r90 top
C69 ".Designator" C1206 39.725,29.4 r90 top
C70 ".Designator" CPOL_TAJ-A_1206_H180 33.45,27.375 r270 top
C71 ".Designator" C0402 20.125,27.875 r180 top
C72 ".Designator" C0402 21,19.75 r90 top
C73 "C73" C0603 19.675,16.075 r270 top
C74 "C74" C0603 38.925,15.925 r90 top
C75 "C75" C0402 18.425,15.825 r90 top
C76 ".Designator" C0603 53.675,12.8 r180 top
C77 "C77" C0402 40.35,12.775 r0 top
C78 ".Designator" C0402 57.5,4 r270 top
C79 ".Designator" C0402 52.1,98 r90 bottom
C80 ".Designator" C0402 31.25,98 r90 bottom
C81 "C81" C0402 19.45,86.85 r180 bottom
C82 ".Designator" C0402 12.75,63.8 r90 bottom
C83 ".Designator" C0402 64.55,33.2 r0 bottom
C84 ".Designator" C1206 63.6,31.65 r0 bottom
C85 ".Designator" CPOL_TAJ-A_1206_H180 66.85,24.6 r180 bottom
C86 ".Designator" C0402 67.55,22.95 r0 bottom
C87 ".Designator" C0402 66.25,22.5 r270 bottom
C88 ".Designator" C0805 64.8,21.7 r270 bottom
C89 ".Designator" C0402 67.55,22.05 r0 bottom
C90 ".Designator" C0402 67.05,9.025 r180 bottom
CARTOUCHE-BOT1 "CARTOUCHE-BOT" CARTOUCHE_STM_BOTTOM 0.275,-31.775 r0 top
CARTOUCHE-TOP1 "CARTOUCHE-TOP" CARTOUCHE_STM_TOP 0.2,-31.8 r0 top
CN1 "CN1" CON_MICROSD_YAMAICHI_PJS008-2003-1 17,105 r90 top locked
CN2 "CN2" CON_USBMICROB_MOLEX_105017-0001_H2P90 57.14,105 r180 top locked
CN3 "CN3" CON_SAMTEC_TSW-102-07-G-S 3.5,90.2 r0 top
CN4 "CN4" CON_SAMTEC_TSW-102-07-G-S 3.5,86.95 r0 top
CN5 "CN5" CON_PHONE-JACK-3P5_HY_PJ3028B 0,79.65 r0 top locked
CN6 "CN6" CON_FISCHER_BL1-10-G 58.88,55.42 r90 top locked
CN7 ".Designator" CON_FISCHER_BL1-8-G 10.62,48.82 r270 top locked
CN8 ".Designator" CON_FISCHER_BL1-8-G 58.88,31.04 r90 top locked
CN9 ".Designator" CON_FISCHER_BL1-6-G 10.62,28.5 r270 top locked
CN10 "CN10" CON_HRS_DF37NB-10DS-04V 18.55,83.4 r90 bottom locked
CN11 ".Designator" CON_TAG-C_TC2050-IDC-NL 63.1,72.5 r180 bottom
CN12 "CN12" CON_FCI_20021311-XXX20XXLF_MOD-MB1299 4.325,65.975 r270 bottom locked
CN13 "CN13" CON_SAMTEC_TSW-102-07-G-S 53.555,52.5 r180 bottom
CN14 "CN14" CON_SAMTEC_TSW-104-07-G-S 67.7,47 r270 bottom locked
CN15 ".Designator" CON_SAMTEC_TMMH-113-01-F-DV 52.8,37 r270 bottom locked
CN16 ".Designator" CON_HRS_FH26-29S-03SHW 40.76,20.063 r0 bottom locked
CN17 "CN17" CON_USBMICROAB_MOLEX_47590-0001_H3 44.275,0 r180 bottom
D1 ".Designator" DIO_SOD323 34.825,88.9 r270 top
D2 ".Designator" DIO_SOD323 36.725,88.9 r270 top
D3 ".Designator" DIO_SOD323 38.625,88.9 r270 top
D4 ".Designator" DIO_SOD323 42.1,85.525 r90 top
D5 ".Designator" DIO_DO216-AA 64.6,36.65 r0 bottom
H1 ".Designator" PTH_M1261-3005-N_3P5X6_M3_H14#1 4.25,100.75 r0 top locked
H2 ".Designator" PTH_M1261-3005-N_3P5X6_M3_H14#1 65.75,100.75 r0 top locked
H3 ".Designator" PTH_M1261-3005-N_3P5X6_M3_H14#2 4.25,4.25 r0 top locked
H4 ".Designator" PTH_M1261-3005-N_3P5X6_M3_H14#1 65.75,4.25 r0 top locked
JP1 ".Designator" CON_SAMTEC_TSW-102-07-G-S 66.65,94.6 r180 top
JP2 ".Designator" CON_SAMTEC_TSW-102-07-G-S 66.65,91.15 r180 top
JP3 ".Designator" CON_SAMTEC_TSM-104-01-X-DV 65.275,83.75 r270 top
L1 ".Designator" L0603 16.95,57.9 r270 top
L2 ".Designator" L0603 66.4,34.25 r270 bottom
L3 ".Designator" L0603 64.2,34.4 r180 bottom
L4 ".Designator" L1210_LQH 67.15,28 r90 bottom
L5 ".Designator" L0603 62.4,23.65 r0 bottom
L6 ".Designator" L0603 62.4,22.15 r0 bottom
L7 ".Designator" L0603 67.2,20.85 r0 bottom
L8 ".Designator" L0603 62.4,20.65 r0 bottom
LCD1 "Comment" LCD_DRAWING_PROJET-MB1274 18.55,83.4 r180 bottom locked
LD1 ".Designator" LED_0603_RED 46,66.425 r180 top
LD2 "LD2" LED_BI-GR_HSMF-A201-A00J1 66.85,66.75 r90 bottom locked
LD3 "LD3" LED_0603_GREEN 67.8,59.675 r0 bottom
LD4 ".Designator" LED_0603_RED 67.8,58.175 r0 bottom
LD5 ".Designator" LED_0603_GREEN 67.8,56.7 r0 bottom
LD6 "LD6" LED_0603_GREEN 67.8,87.85 r0 bottom
LD7 ".Designator" LED_0603_GREEN 48.15,7.85 r270 bottom
LD8 ".Designator" LED_0603_RED 46.2,7.85 r270 bottom
M1 "M1" MOD_WIFI_INVENTEK-SYSTEMS_ISM43362-M3G-L44-E-SPI-CXX 23.4,8.5 r180 bottom locked
MIRE1 "MIRE1" MIRE_PLACE_SMD_0P8MM 6.775,96.075 r0 top
MIRE2 "MIRE2" MIRE_PLACE_SMD_0P8MM 2,18.6 r0 top
MIRE3 "MIRE3" MIRE_PLACE_SMD_0P8MM 58.6,8.675 r0 top
MIRE4 "MIRE4" MIRE_PLACE_SMD_0P8MM 4.325,95.75 r180 bottom
MIRE5 "MIRE5" MIRE_PLACE_SMD_0P8MM 7.875,19.15 r180 bottom
MIRE6 "MIRE6" MIRE_PLACE_SMD_0P8MM 58.6,8.675 r180 bottom
R1 "R1" R0402 26.5,103.425 r270 top
R2 ".Designator" R0402 60.3,99.2 r0 top
R3 ".Designator" R0402 56.05,98.7 r90 top
R4 ".Designator" R0402 57.15,98.7 r270 top
R5 ".Designator" R0402 61.2,98.125 r180 top
R6 ".Designator" R0402 61.2,97.05 r0 top
R7 ".Designator" R0402 51.275,91.2 r90 top
R8 ".Designator" R0402 52.825,90.9 r0 top
R9 ".Designator" R0402 44.125,87.6 r0 top
R10 ".Designator" R0402 44.125,86.55 r180 top
R11 ".Designator" R0402 44.125,85.5 r180 top
R12 ".Designator" R0603 8.125,84.425 r90 top
R13 ".Designator" R0402 30.05,84.85 r0 top
R14 ".Designator" R0402 44.125,84.45 r0 top
R15 ".Designator" R0603 56.875,82.45 r180 top
R16 ".Designator" R0402 46.425,78.4 r270 top
R17 ".Designator" R0402 47.475,78.4 r270 top
R18 ".Designator" R0402 53.625,78.4 r270 top
R19 ".Designator" R0603 56.325,78.05 r90 top
R20 ".Designator" R0402 26.7,73.425 r90 top
R21 ".Designator" R0402 27.85,73.425 r90 top
R22 ".Designator" R0603 12,72.7 r270 top
R23 ".Designator" R0603 13.4,72.7 r270 top
R24 ".Designator" R0402 42.025,72.225 r270 top
R25 ".Designator" R0603 11.05,70.85 r180 top
R26 ".Designator" R0603 20.15,70.425 r0 top
R27 ".Designator" R0402 50.2,70.075 r270 top
R28 ".Designator" R0603 22.85,69.5 r180 top
R29 ".Designator" R0603 11.05,69.45 r0 top
R30 ".Designator" R0402 19.825,69.225 r180 top
R31 ".Designator" R0402 36.1,68.425 r180 top
R32 ".Designator" R0402 9.65,68.25 r0 top
R33 ".Designator" R0603 20.15,68.05 r180 top
R34 ".Designator" R0402 65.725,67.5 r180 top
R35 ".Designator" R0402 9.65,67.2 r0 top
R36 ".Designator" R0402 43.5,66.425 r180 top
R37 ".Designator" R0402 48.6,66.425 r0 top
R38 ".Designator" R0402 65.725,66 r180 top
R39 ".Designator" R0402 20.225,64.45 r270 top
R40 ".Designator" R0402 62.425,63.025 r0 top
R41 "R41" R0402 67.15,61.6 r0 top
R42 "R42" R0402 67.15,60.45 r0 top
R43 ".Designator" R0603 40.05,58.4 r90 top
R44 ".Designator" R0402 27.6,58.45 r180 top
R45 ".Designator" R0402 29.3,58.45 r0 top
R46 ".Designator" R0402 33,58.05 r90 top
R47 ".Designator" R0402 35.1,57.7 r180 top
R48 ".Designator" R0402 36.8,57.7 r0 top
R49 "R49" R0402 27.6,57.4 r180 top
R50 ".Designator" R0402 29.3,57.4 r0 top
R51 ".Designator" R0402 23.6,56.6 r180 top
R52 ".Designator" R0402 43.65,51.95 r270 top
R53 ".Designator" R0402 44.75,51.95 r90 top
R54 ".Designator" R0402 43.65,49.6 r90 top
R55 ".Designator" R0402 44.75,49.6 r90 top
R56 ".Designator" R0402 33.7,30.9 r270 top
R57 ".Designator" R0402 34.75,30.9 r270 top
R58 ".Designator" R0603 31.475,27.825 r90 top
R59 ".Designator" R0402 25.9,22.3 r180 top
R60 ".Designator" R0402 25.9,21.25 r0 top
R61 ".Designator" R0402 17.675,20.175 r0 top
R62 ".Designator" R0402 24.55,20.075 r0 top
R63 ".Designator" R0402 49.425,16.625 r0 top
R64 ".Designator" R0402 51.275,16.625 r0 top
R65 ".Designator" R0402 53.325,16.425 r180 top
R66 ".Designator" R0402 53.325,15.35 r0 top
R67 ".Designator" R0603 53.675,14.15 r0 top
R68 "R68" R0402 33.925,13.5 r90 top
R69 ".Designator" R0402 53.375,11.6 r0 top
R70 ".Designator" R0402 55.075,11.6 r180 top
R71 ".Designator" R0402 37.575,11.35 r180 top
R72 ".Designator" R0402 61.85,8.575 r0 top
R73 ".Designator" R0402 56.375,4 r270 top
R74 ".Designator" R0402 20.75,3.925 r90 top
R75 "R75" R0402 22.2,3.925 r90 top
R76 "R76" R0402 26.825,3.925 r90 top
R77 "R77" R0402 28.05,3.925 r270 top
R78 "R78" R0402 29.5,3.925 r270 top
R79 ".Designator" R0603 10.2,98.9 r90 bottom
R80 ".Designator" R0402 31.25,96.1 r270 bottom
R81 ".Designator" R0402 19.55,92.15 r90 bottom
R82 ".Designator" R0402 18.45,92.15 r90 bottom
R83 ".Designator" R0402 17.35,92.15 r90 bottom
R84 ".Designator" R0402 12.925,92.15 r90 bottom
R85 ".Designator" R0402 11.825,92.15 r90 bottom
R86 ".Designator" R0402 52.575,81.1 r270 bottom
R87 ".Designator" R0402 51.475,81.1 r270 bottom
R88 ".Designator" R0402 19.45,79.85 r0 bottom
R89 ".Designator" R0603 67.425,78.025 r90 bottom
R90 ".Designator" R0603 65.625,78.025 r90 bottom
R91 ".Designator" R0603 60.575,78.025 r90 bottom
R92 ".Designator" R0603 58.725,78.025 r90 bottom
R93 ".Designator" R0402 65.5,59.675 r0 bottom
R94 ".Designator" R0402 65.5,58.175 r180 bottom
R95 ".Designator" R0603 7.85,57.7 r0 bottom
R96 ".Designator" R0402 65.5,56.7 r180 bottom
R97 ".Designator" R0402 65.5,87.85 r0 bottom
R98 ".Designator" R0402 66.7,32.15 r180 bottom
R99 ".Designator" R0402 66.7,31.1 r0 bottom
R100 ".Designator" R0402 64.1,25.2 r90 bottom
R101 ".Designator" R0603 62.4,25.3 r180 bottom
R102 ".Designator" R0402 4.95,24.05 r180 bottom
R103 ".Designator" R0402 47.575,21.55 r90 bottom
R104 ".Designator" R0402 4.95,21.2 r180 bottom
R105 ".Designator" R0402 42.85,17.15 r90 bottom
R106 ".Designator" R0402 68.325,17.35 r180 bottom
R107 ".Designator" R0402 48.15,10 r90 bottom
R108 ".Designator" R0402 46.2,10 r270 bottom
R109 ".Designator" R0402 65.15,9.025 r0 bottom
SB1 ".Designator" SOLDER-BRIDGE_R0603-0R 45.375,102.575 r90 top
SB2 ".Designator" SOLDER-BRIDGE_R0603-0R 33.025,87.35 r270 top
SB3 ".Designator" SOLDER-BRIDGE_R0603-0R 54.875,77.85 r90 top
SB4 ".Designator" SOLDER-BRIDGE_R0603-0R 46.1,73.5 r180 top
SB5 ".Designator" SOLDER-BRIDGE_R0603-0R 63,59.05 r90 top
SB6 ".Designator" SOLDER-BRIDGE_R0603-0R 48.85,54.5 r270 top
SB7 ".Designator" SOLDER-BRIDGE_R0603-0R 16.075,52.775 r270 top
SB8 "SB8" SOLDER-BRIDGE_R0603-0R 35.325,14.45 r90 top
SB9 "SB9" SOLDER-BRIDGE_R0603-0R 36.8,14.45 r90 top
SB10 "SB10" SOLDER-BRIDGE_R0603-0R 21.475,6.975 r270 top
SB11 "SB11" SOLDER-BRIDGE_R0603-0R 37.05,4.25 r0 top
SB12 "SB12" SOLDER-BRIDGE_R0603-0R 37.05,2.825 r0 top
SB13 ".Designator" SOLDER-BRIDGE_R0603-0R 26.2,87.4 r270 bottom
SB14 ".Designator" SOLDER-BRIDGE_R0603-0R 24.4,87.4 r270 bottom
SB15 ".Designator" SOLDER-BRIDGE_R0603-0R 67.425,80.875 r270 bottom
SB16 ".Designator" SOLDER-BRIDGE_R0603-0R 65.625,80.875 r270 bottom
SB17 ".Designator" SOLDER-BRIDGE_R0603-0R 60.575,80.875 r270 bottom
SB18 ".Designator" SOLDER-BRIDGE_R0603-0R 58.725,80.875 r270 bottom
SB19 ".Designator" SOLDER-BRIDGE_R0603-0R 7.4,25.4 r0 bottom
SB20 ".Designator" SOLDER-BRIDGE_R0603-0R 7.4,24.05 r0 bottom
SB21 ".Designator" SOLDER-BRIDGE_R0603-0R 7.4,22.65 r0 bottom
SB22 ".Designator" SOLDER-BRIDGE_R0603-0R 51.675,21.15 r270 bottom
SB23 ".Designator" SOLDER-BRIDGE_R0603-0R 50.125,21.15 r270 bottom
SB24 ".Designator" SOLDER-BRIDGE_R0603-0R 7.4,21.3 r0 bottom
T1 ".Designator" NPN_SOT23 61.425,94.65 r270 top
T2 "T2" NPN_SOT23 66.65,57.675 r180 top
T3 ".Designator" NPN_SOT23 53.975,9.35 r270 top
TP1 "TP1" TP_SMD_1MM 27.625,85.275 r180 top
TP2 "TP2" TP_SMD_1MM 34.625,77.275 r180 top
TP3 ".Designator" TP_SMD_1MM 26.825,75.95 r90 top
TP4 ".Designator" TP_SMD_1MM 25.05,73.475 r90 top
TP5 "TP5" TP_SMD_1MM 9.925,73.4 r180 top
TP6 ".Designator" TP_SMD_1MM 38.4,70.5 r90 top
TP7 "TP7" TP_SMD_1MM 24.45,67.86 r180 top
TP8 "TP8" TP_SMD_1MM 8.025,65.575 r180 top
TP9 "TP9" TP_SMD_1MM 34.45,63.95 r90 top
TP10 "TP10" TP_SMD_1MM 14.775,57.075 r180 top
TP11 "TP11" TP_SMD_1MM 48.8,49.525 r180 top
TP12 "TP12" TP_SMD_1MM 17.825,49.425 r90 top
TP13 "TP13" TP_SMD_1MM 44.95,43.1 r180 top
TP14 "TP14" TP_SMD_1MM 47.95,41.85 r180 top
TP15 "TP15" TP_SMD_1MM 46.325,39.95 r180 top
TP16 "TP16" TP_SMD_1MM 29.9,23.85 r180 top
TP17 "TP17" TP_SMD_2MM 20.82,12.365 r0 top
TP18 "TP18" TP_SMD_2MM 23.36,12.365 r0 top
TP19 "TP19" TP_SMD_2MM 25.9,12.365 r0 top
TP20 "TP20" TP_SMD_2MM 28.44,12.365 r0 top
TP21 "TP21" TP_SMD_2MM 30.98,12.365 r270 top
TP22 "TP22" TP_SMD_1MM 24.275,3.925 r270 top
U1 ".Designator" MIC_STM_MP23DB01MMTR 28.7,102.425 r0 top locked
U2 ".Designator" MIC_STM_MP23DB01MMTR 49.7,102.425 r0 top locked
U3 ".Designator" REG_SOT223-TAB 36.05,96.675 r180 top
U4 ".Designator" REG_SOT223-TAB 43.575,96.675 r180 top
U5 "U5" ESD_SOT666 58.325,95.875 r180 top
U6 ".Designator" ICC_LQFP48_7X7_P050 50.575,85.2 r0 top
U7 ".Designator" REG_SOT23-5L 35.925,84.15 r270 top
U8 ".Designator" ICC_TSSOP16_5P1X4P5_P065 27.2,81.5 r180 top
U9 ".Designator" ICC_V-PDFN-8_8X6_P127 32.95,72.325 r180 top
U10 ".Designator" ICC_SO8_5X4_P127 46.05,69.875 r90 top
U11 ".Designator" ICC_W-CSP-BGA72_4P511X4P023_P050 15.65,68.35 r270 top locked
U12 ".Designator" REG_SOT23-5L 8.8,61.2 r270 top
U13 "U13" ICC_LQFP144_20X20_P050 30.95,44.3 r270 top locked
U14 "U14" ICC_MINI-BGA48_6X8_P075 20.6,24.05 r270 top locked
U15 ".Designator" MOS_SOT23-5L 50.525,14 r90 top
U16 ".Designator" MIC_HCLGA_3X4X1_4LD 49.7,97 r0 bottom locked
U17 ".Designator" MIC_HCLGA_3X4X1_4LD 28.7,97 r0 bottom locked
U18 ".Designator" ICC_QFN8-EPAD_3X3_P065 63.3,28 r180 bottom
U19 "U19" ESD_SOT666 43.95,6.95 r0 bottom
U20 ".Designator" ESD_ST0201 46.175,5.875 r0 bottom
U21 "U21" ESD_QFN2_1P6X1_P125 41.225,6.4 r180 bottom value=ESDA7P60-1U1M
X1 ".Designator" CRY_NX3225GD_2P 50.075,77.7 r180 top
X2 ".Designator" CRY_NX3225GD_2P 28.45,60.55 r180 top
X3 ".Designator" CRY_NX3215SA_2P 35.95,59.35 r180 top

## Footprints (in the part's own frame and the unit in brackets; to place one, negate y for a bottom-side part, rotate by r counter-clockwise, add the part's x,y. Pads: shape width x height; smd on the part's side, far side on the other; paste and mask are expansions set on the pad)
C0402 [mm]
  rect 0.51x0.56 smd mask+0.05: 1(-0.45,0) 2(0.45,0)
  silkscreen extent -0.72,-0.35 0.72,0.35, body extent -0.5,-0.3 0.5,0.3, height 0.4
C0603 [mm]
  rect 0.64x0.89 smd mask+0.05: 1(-0.7,0) 2(0.7,0)
  silkscreen extent -1.05,-0.55 1.02,0.55, body extent -0.9,-0.5 0.9,0.5, height 1.4
C0805 [mm]
  rect 0.9x1.4 smd mask+0.05: 1(-0.85,0) 2(0.85,0)
  silkscreen extent -1.3,-0.77 1.3,0.77, body extent -1.1,-0.7 1.1,0.7, height 1.35
C1206 [mm]
  rect 1.4x1.78 smd mask+0.05: 1(-1.4,0) 2(1.4,0)
  silkscreen extent -2.12,-0.97 2.15,0.97, body extent -1.7,-0.9 1.7,0.9, height 1.8
CARTOUCHE_STM_BOTTOM [mm]
CARTOUCHE_STM_TOP [mm]
CON_FCI_20021311-XXX20XXLF_MOD-MB1299 [mm] "MB1299 MICROPHONE MEMS"
  rect 1x1 / inner round 1 / far side rect 1x1 hole 0.7 mask+0.05: 1(5.715,0.635)
  round 1 hole 0.7 mask+0.05: 2(5.715,-0.635) 3(4.445,0.635) 4(4.445,-0.635) 5(3.175,0.635) 6(3.175,-0.635) 7(1.905,0.635) 8(1.905,-0.635) 9(0.635,0.635) 10(0.635,-0.635) 11(-0.635,0.635) 12(-0.635,-0.635) 13(-1.905,0.635) 14(-1.905,-0.635) 15(-3.175,0.635) 16(-3.175,-0.635) 17(-4.445,0.635) 18(-4.445,-0.635) 19(-5.715,0.635) 20(-5.715,-0.635)
  silkscreen extent -9.13,-6.99 9.27,7.01, body extent -9.13,-6.99 9.27,7.01, height 6.9
CON_FISCHER_BL1-6-G [mm]
  rect 1.8x1.8 / inner round 1.8 / far side rect 1.8x1.8 hole 0.9 mask+0.05: 1(-6.35,0)
  round 1.8 hole 0.9 mask+0.05: 2(-3.81,0) 3(-1.27,0) 4(1.27,0) 5(3.81,0) 6(6.35,0)
  silkscreen extent -7.62,-1.25 7.62,1.25, body extent -7.62,-1.25 7.62,1.25, height 8
CON_FISCHER_BL1-8-G [mm]
  rect 1.8x1.8 / inner round 1.8 / far side rect 1.8x1.8 hole 0.9 mask+0.05: 1(-8.89,0)
  round 1.8 hole 0.9 mask+0.05: 2(-6.35,0) 3(-3.81,0) 4(-1.27,0) 5(1.27,0) 6(3.81,0) 7(6.35,0) 8(8.89,0)
  silkscreen extent -10.16,-1.25 10.16,1.25, body extent -10.16,-1.25 10.16,1.25, height 8
CON_FISCHER_BL1-10-G [mm]
  rect 1.8x1.8 / inner round 1.8 / far side rect 1.8x1.8 hole 0.9 mask+0.05: 1(-11.43,0)
  round 1.8 hole 0.9 mask+0.05: 2(-8.89,0) 3(-6.35,0) 4(-3.81,0) 5(-1.27,0) 6(1.27,0) 7(3.81,0) 8(6.35,0) 9(8.89,0) 10(11.43,0)
  silkscreen extent -12.7,-1.25 12.71,1.25, body extent -12.7,-1.25 12.7,1.25, height 8
CON_HRS_DF37NB-10DS-04V [mm]
  rect 0.2x0.63 smd mask+0.05: 1(0.8,-1.325) 2(0.4,-1.325) 3(0,-1.325) 4(-0.4,-1.325) 5(-0.8,-1.325) 6(-0.8,1.325) 7(-0.4,1.325) 8(0,1.325) 9(0.4,1.325) 10(0.8,1.325)
  rect 0.38x1.1 smd mask+0.05: MT1(-2.04,0) MT2(2.04,0)
  silkscreen extent -2.26,-1.26 2.26,1.26, body extent -2.32,-1.32 2.32,1.32, height 1.06
CON_HRS_FH26-29S-03SHW [mm]
  rect 0.3x0.8 smd mask+0.05: 1(-4.2,-1.437) 3(-3.6,-1.437) 5(-3,-1.437) 7(-2.4,-1.437) 9(-1.8,-1.437) 11(-1.2,-1.437) 13(-0.6,-1.437) 15(0,-1.437) 17(0.6,-1.437) 19(1.2,-1.437) 21(1.8,-1.437) 23(2.4,-1.437) 25(3,-1.437) 27(3.6,-1.437) 29(4.2,-1.437)
  rect 0.3x0.65 smd mask+0.05: 2(-3.9,1.438) 4(-3.3,1.438) 6(-2.7,1.438) 8(-2.1,1.438) 10(-1.5,1.438) 12(-0.9,1.438) 14(-0.3,1.438) 16(0.3,1.438) 18(0.9,1.438) 20(1.5,1.438) 22(2.1,1.438) 24(2.7,1.438) 26(3.3,1.438) 28(3.9,1.438)
  rect 0.4x0.95 smd mask+0.05: MT1(-4.9,-1.162) MT2(4.9,-1.162)
  silkscreen extent -5.1,-1.99 5.1,1.31, body extent -5.16,-2.05 5.16,1.55, height 8.13
CON_MICROSD_YAMAICHI_PJS008-2003-1 [mm]
  rect 1.6x0.8 smd paste+0 mask+0.05: 1(-15.6,-2.525) 2(-15.6,-1.425) 3(-15.6,-0.325) 4(-15.6,0.775) 5(-15.6,1.875) 6(-15.6,2.975) 7(-15.6,4.075) 8(-15.6,5.175)
  rect 1.6x0.85 smd paste+0 mask+0.05: 9(-15.6,6.325)
  rect 1.4x1.95 smd paste+0 mask+0.05: 10(-5.4,7.225)
  rect 3.5x1.5 smd paste+0 mask+0.05: 11(-2.45,7.45)
  rect 3.5x1.4 smd paste+0 mask+0.05: 12(-2.45,-7.5)
  rect 3.5x1.6 smd paste+0 mask+0.05: 13(-13.45,-7.4)
  rect 3.1x1.2 smd paste+0 mask+0.05: 14(-13.95,7.6)
  round 0 hole 0.65 unplated mask+0.05: NPTH1(-9.8,-4)
  round 0 hole 0.7 unplated mask+0.05: NPTH2(-9.8,3.55)
  silkscreen extent -15.32,-7.25 5.65,7.25, body extent -15.25,-7.25 -0.45,7.42, height 2
CON_PHONE-JACK-3P5_HY_PJ3028B [mm]
  rect 1.5x2.5 smd mask+0.05: 2(1.25,-3.45) 7(2.85,3.45)
  rect 2x2.5 smd mask+0.05: 3(4,-3.45) 4(5.8,3.45) 6(13.2,-3.45)
  rect 2.5x2 smd mask+0.05: 5(17.25,0.75)
  round 0.5 hole 2 unplated mask+0.1: MT1(5,0) MT2(12,0)
  Multi-Layer keep-out circle w0.01: c12,0 r1.25
  Multi-Layer keep-out circle w0.01: c5,0 r1.25
  silkscreen extent -0.9,-3.7 16,3, body extent -0.9,-3 16,3, height 5
CON_SAMTEC_TMMH-113-01-F-DV [mm]
  rect 1x3 smd mask+0.05: 1(-12,-2.3) 2(-12,2.3) 3(-10,-2.3) 4(-10,2.3) 5(-8,-2.3) 6(-8,2.3) 7(-6,-2.3) 8(-6,2.3) 9(-4,-2.3) 10(-4,2.3) 11(-2,-2.3) 12(-2,2.3) 13(0,-2.3) 14(0,2.3) 15(2,-2.3) 16(2,2.3) 17(4,-2.3) 18(4,2.3) 19(6,-2.3) 20(6,2.3) 21(8,-2.3) 22(8,2.3) 23(10,-2.3) 24(10,2.3) 25(12,-2.3) 26(12,2.3)
  silkscreen extent -13,-3.18 13,3.18, body extent -13.06,-3.52 13.06,3.52, height 5.71
CON_SAMTEC_TSM-104-01-X-DV [mm]
  rect 1.3x2.9 smd paste+0 mask+0.05: 1(-3.81,-2.55) 2(-3.81,2.55) 3(-1.27,-2.55) 4(-1.27,2.55) 5(1.27,-2.55) 6(1.27,2.55) 7(3.81,-2.55) 8(3.81,2.55)
  silkscreen extent -5.24,-2.22 5.24,2.22, body extent -5.24,-3.85 5.24,3.85, height 9.65
CON_SAMTEC_TSW-102-07-G-S [mm]
  rect 1.85x1.85 / inner round 1.85 / far side rect 1.85x1.85 hole 1 mask+0.05: 1(-1.27,0)
  round 1.85 hole 1 mask+0.05: 2(1.27,0)
  silkscreen extent -2.58,-1.3 2.58,1.3, body extent -2.67,-1.3 2.58,1.3, height 8.38
CON_SAMTEC_TSW-104-07-G-S [mm]
  rect 1.85x1.85 / inner round 1.85 / far side rect 1.85x1.85 hole 1 mask+0.05: 1(-3.81,0)
  round 1.85 hole 1 mask+0.05: 2(-1.27,0) 3(1.27,0) 4(3.81,0)
  silkscreen extent -5.12,-1.3 5.12,1.3, body extent -5.21,-1.37 5.18,1.37, height 8.38
CON_TAG-C_TC2050-IDC-NL [mm]
  round 0.9 smd paste+0 mask+0.05: 1(-2.54,-0.635) 2(-1.27,-0.635) 3(0,-0.635) 4(1.27,-0.635) 5(2.54,-0.635) 6(2.54,0.635) 7(1.27,0.635) 8(0,0.635) 9(-1.27,0.635) 10(-2.54,0.635)
  round 0 hole 1.1 unplated mask+0.05: 11(-3.81,0) 12(3.81,-1.015) 13(3.81,1.015)
  Multi-Layer keep-out circle w0.01: c3.81,-1.015 r0.75
  Multi-Layer keep-out circle w0.01: c3.81,1.015 r0.75
  Multi-Layer keep-out circle w0.01: c-3.81,0 r0.75
  silkscreen extent -6.22,-3.4 6.22,3.33, body extent -6.28,-3.46 6.28,3.39, height 13
CON_USBMICROAB_MOLEX_47590-0001_H3 [mm]
  rect 0.4x1.35 smd mask+0.05: 1(1.3,4.125) 2(0.65,4.125) 3(0,4.125) 4(-0.65,4.125) 5(-1.3,4.125)
  oval 1.05x1.25 hole 0.65 slot 0.85 at 90 deg mask+0.05: 6(-2.225,4.45) 7(2.225,4.45)
  rrect50% 1.375x1.9 hole 0.6 slot 1.3 at 90 deg copper offset 0.188,0 mask+0.05: 8(-4.175,1.45)
  rrect50% 1.375x1.9 hole 0.6 slot 1.3 at 90 deg copper offset -0.188,0 mask+0.05: 9(4.175,1.45)
  rect 2.9x1.9 smd mask+0.05: 10(0,1.45)
  oval 0.85x2.425 hole 0.85 slot 2.425 at 90 deg unplated mask+0.1: 11(-2.375,0.8) 12(2.375,0.8)
  silkscreen extent -4.1,-1.3 4.1,4.3, body extent -4.32,-1.36 4.33,4.6, height 3
CON_USBMICROB_MOLEX_105017-0001_H2P90 [mm]
  rect 0.4x1.35 smd mask+0.05: 1(-1.3,4.15) 2(-0.65,4.15) 3(0,4.15) 4(0.65,4.15) 5(1.3,4.15)
  round 1.5 hole 0.9 mask+0.05: 6(-2.5,4.15) 7(2.5,4.15)
  oval 1.2x1.9 hole 0.6 slot 1.3 at 90 deg mask+0.05: 8(3.5,1.45) 9(-3.5,1.45)
  rect 1.5x1.9 smd mask+0.05: 10(-1,1.45) 11(1,1.45)
  Top Layer region: -3.5,2.4 -2.3,2.4 -2.3,0.5 -3.5,0.5 -3.5,2.4
  Top Layer region: 2.3,2.4 3.5,2.4 3.5,0.5 2.3,0.5 2.3,2.4
  silkscreen extent -4,-0.7 4,4.6, body extent -4.1,-1.15 4.1,4.66, height 2.9
CPOL_TAJ-A_1206_H180 [mm]
  rect 1.45x1.6 smd mask+0.05: 1(-1.175,0) 2(1.175,0)
  silkscreen extent -2.15,-1.05 1.7,1.05, body extent -1.7,-0.9 1.7,0.9, height 1.8
CRY_NX3215SA_2P [mm]
  rect 1x1.8 smd mask+0.05: 1(-1.25,0) 2(1.25,0)
  body extent -1.65,-0.8 1.65,0.8, height 0.9
CRY_NX3225GD_2P [mm]
  rect 1.5x2.7 smd mask+0.05: 1(-0.95,0) 2(0.95,0)
  silkscreen extent -0.1,-1.3 0.1,1.3, body extent -1.65,-1.3 1.65,1.3, height 1
DIO_DO216-AA [mm]
  rect 1.38x0.75 smd mask+0.05: 1(1.515,0)
  rect 2.32x1.1 smd mask+0.05: 2(-1.045,0)
  Top Layer region: -1.705,1.015 0.115,1.015 0.115,-1.015 -1.705,-1.015
  silkscreen extent -2.25,-1.12 0.72,1.12, body extent -2.02,-1.02 1.83,1.02, height 1.15
DIO_SOD323 [mm]
  rect 1.06x0.54 smd mask+0.05: 1(-1.07,0) 2(1.07,0)
  silkscreen extent -0.9,-0.72 0.9,0.72, body extent -1.3,-0.78 1.3,0.78, height 1.17
ESD_QFN2_1P6X1_P125 [mm]
  rect 0.55x0.8 smd mask+0.05: 1(-0.625,0) 2(0.625,0)
  silkscreen extent -1,-0.55 0.85,0.55, body extent -0.85,-0.55 0.85,0.55, height 0.61
ESD_SOT666 [mm]
  rect 0.3x0.99 smd mask+0.05: 1(-0.5,-0.805) 2(0,-0.805) 3(0.5,-0.805) 4(0.5,0.805) 5(0,0.805) 6(-0.5,0.805)
  silkscreen extent -0.85,-0.65 0.85,0.65, body extent -0.85,-0.8 0.85,0.8, height 0.6
ESD_ST0201 [mm]
  rect 0.425x0.33 smd mask+0.05: 1(-0.312,0) 2(0.312,0)
  silkscreen extent -0.55,-0.3 0.33,0.3, body extent -0.34,-0.18 0.34,0.18, height 0.34
ICC_LQFP48_7X7_P050 [mm]
  rect 0.3x1.2 smd mask+0.05: 1(-2.75,-4.25) 2(-2.25,-4.25) 3(-1.75,-4.25) 4(-1.25,-4.25) 5(-0.75,-4.25) 6(-0.25,-4.25) 7(0.25,-4.25) 8(0.75,-4.25) 9(1.25,-4.25) 10(1.75,-4.25) 11(2.25,-4.25) 12(2.75,-4.25) 25(2.75,4.25) 26(2.25,4.25) 27(1.75,4.25) 28(1.25,4.25) 29(0.75,4.25) 30(0.25,4.25) 31(-0.25,4.25) 32(-0.75,4.25) 33(-1.25,4.25) 34(-1.75,4.25) 35(-2.25,4.25) 36(-2.75,4.25)
  rect 1.2x0.3 smd mask+0.05: 13(4.25,-2.75) 14(4.25,-2.25) 15(4.25,-1.75) 16(4.25,-1.25) 17(4.25,-0.75) 18(4.25,-0.25) 19(4.25,0.25) 20(4.25,0.75) 21(4.25,1.25) 22(4.25,1.75) 23(4.25,2.25) 24(4.25,2.75) 37(-4.25,2.75) 38(-4.25,2.25) 39(-4.25,1.75) 40(-4.25,1.25) 41(-4.25,0.75) 42(-4.25,0.25) 43(-4.25,-0.25) 44(-4.25,-0.75) 45(-4.25,-1.25) 46(-4.25,-1.75) 47(-4.25,-2.25) 48(-4.25,-2.75)
  silkscreen extent -3.52,-3.52 3.52,3.52, body extent -4.5,-4.5 4.5,4.5, height 1.6
ICC_LQFP144_20X20_P050 [mm]
  rect 1.35x0.3 smd mask+0.05: 1(-10.625,8.75) 2(-10.625,8.25) 3(-10.625,7.75) 4(-10.625,7.25) 5(-10.625,6.75) 6(-10.625,6.25) 7(-10.625,5.75) 8(-10.625,5.25) 9(-10.625,4.75) 10(-10.625,4.25) 11(-10.625,3.75) 12(-10.625,3.25) 13(-10.625,2.75) 14(-10.625,2.25) 15(-10.625,1.75) 16(-10.625,1.25) 17(-10.625,0.75) 18(-10.625,0.25) 19(-10.625,-0.25) 20(-10.625,-0.75) 21(-10.625,-1.25) 22(-10.625,-1.75) 23(-10.625,-2.25) 24(-10.625,-2.75) 25(-10.625,-3.25) 26(-10.625,-3.75) 27(-10.625,-4.25) 28(-10.625,-4.75) 29(-10.625,-5.25) 30(-10.625,-5.75) 31(-10.625,-6.25) 32(-10.625,-6.75) 33(-10.625,-7.25) 34(-10.625,-7.75) 35(-10.625,-8.25) 36(-10.625,-8.75) 73(10.625,-8.75) 74(10.625,-8.25) 75(10.625,-7.75) 76(10.625,-7.25) 77(10.625,-6.75) 78(10.625,-6.25) 79(10.625,-5.75) 80(10.625,-5.25) 81(10.625,-4.75) 82(10.625,-4.25) 83(10.625,-3.75) 84(10.625,-3.25) 85(10.625,-2.75) 86(10.625,-2.25) 87(10.625,-1.75) 88(10.625,-1.25) 89(10.625,-0.75) 90(10.625,-0.25) 91(10.625,0.25) 92(10.625,0.75) 93(10.625,1.25) 94(10.625,1.75) 95(10.625,2.25) 96(10.625,2.75) 97(10.625,3.25) 98(10.625,3.75) 99(10.625,4.25) 100(10.625,4.75) 101(10.625,5.25) 102(10.625,5.75) 103(10.625,6.25) 104(10.625,6.75) 105(10.625,7.25) 106(10.625,7.75) 107(10.625,8.25) 108(10.625,8.75)
  rect 0.3x1.35 smd mask+0.05: 37(-8.75,-10.625) 38(-8.25,-10.625) 39(-7.75,-10.625) 40(-7.25,-10.625) 41(-6.75,-10.625) 42(-6.25,-10.625) 43(-5.75,-10.625) 44(-5.25,-10.625) 45(-4.75,-10.625) 46(-4.25,-10.625) 47(-3.75,-10.625) 48(-3.25,-10.625) 49(-2.75,-10.625) 50(-2.25,-10.625) 51(-1.75,-10.625) 52(-1.25,-10.625) 53(-0.75,-10.625) 54(-0.25,-10.625) 55(0.25,-10.625) 56(0.75,-10.625) 57(1.25,-10.625) 58(1.75,-10.625) 59(2.25,-10.625) 60(2.75,-10.625) 61(3.25,-10.625) 62(3.75,-10.625) 63(4.25,-10.625) 64(4.75,-10.625) 65(5.25,-10.625) 66(5.75,-10.625) 67(6.25,-10.625) 68(6.75,-10.625) 69(7.25,-10.625) 70(7.75,-10.625) 71(8.25,-10.625) 72(8.75,-10.625) 109(8.75,10.625) 110(8.25,10.625) 111(7.75,10.625) 112(7.25,10.625) 113(6.75,10.625) 114(6.25,10.625) 115(5.75,10.625) 116(5.25,10.625) 117(4.75,10.625) 118(4.25,10.625) 119(3.75,10.625) 120(3.25,10.625) 121(2.75,10.625) 122(2.25,10.625) 123(1.75,10.625) 124(1.25,10.625) 125(0.75,10.625) 126(0.25,10.625) 127(-0.25,10.625) 128(-0.75,10.625) 129(-1.25,10.625) 130(-1.75,10.625) 131(-2.25,10.625) 132(-2.75,10.625) 133(-3.25,10.625) 134(-3.75,10.625) 135(-4.25,10.625) 136(-4.75,10.625) 137(-5.25,10.625) 138(-5.75,10.625) 139(-6.25,10.625) 140(-6.75,10.625) 141(-7.25,10.625) 142(-7.75,10.625) 143(-8.25,10.625) 144(-8.75,10.625)
  silkscreen extent -10.1,-10.1 10.1,10.1, body extent -11,-11 11,11, height 1.6
ICC_MINI-BGA48_6X8_P075 [mm]
  round 0.32 smd mask+0.05: A1(-1.875,2.625) A2(-1.125,2.625) A3(-0.375,2.625) A4(0.375,2.625) A5(1.125,2.625) A6(1.875,2.625) B1(-1.875,1.875) B2(-1.125,1.875) B3(-0.375,1.875) B4(0.375,1.875) B5(1.125,1.875) B6(1.875,1.875) C1(-1.875,1.125) C2(-1.125,1.125) C3(-0.375,1.125) C4(0.375,1.125) C5(1.125,1.125) C6(1.875,1.125) D1(-1.875,0.375) D2(-1.125,0.375) D3(-0.375,0.375) D4(0.375,0.375) D5(1.125,0.375) D6(1.875,0.375) E1(-1.875,-0.375) E2(-1.125,-0.375) E3(-0.375,-0.375) E4(0.375,-0.375) E5(1.125,-0.375) E6(1.875,-0.375) F1(-1.875,-1.125) F2(-1.125,-1.125) F3(-0.375,-1.125) F4(0.375,-1.125) F5(1.125,-1.125) F6(1.875,-1.125) G1(-1.875,-1.875) G2(-1.125,-1.875) G3(-0.375,-1.875) G4(0.375,-1.875) G5(1.125,-1.875) G6(1.875,-1.875) H1(-1.875,-2.625) H2(-1.125,-2.625) H3(-0.375,-2.625) H4(0.375,-2.625) H5(1.125,-2.625) H6(1.875,-2.625)
  silkscreen extent -3.18,-4.05 3.05,4.18, body extent -3.05,-4.05 3.06,4.06, height 1.2
ICC_QFN8-EPAD_3X3_P065 [mm]
  rect 0.4x0.6 smd paste+0 mask+0.05: 1(-0.975,-1.4) 2(-0.325,-1.4) 3(0.325,-1.4) 4(0.975,-1.4) 5(0.975,1.4) 6(0.325,1.4) 7(-0.325,1.4) 8(-0.975,1.4)
  rect 3.6x1.9 smd paste+0 mask+0: 9(0,0)
  silkscreen extent -1.58,-1.58 1.58,1.58, body extent -1.58,-1.58 1.58,1.58, height 1
ICC_SO8_5X4_P127 [mm]
  rect 0.7x1.75 smd mask+0.05: 1(-1.905,-2.375) 2(-0.635,-2.375) 3(0.635,-2.375) 4(1.905,-2.375) 5(1.905,2.375) 6(0.635,2.375) 7(-0.635,2.375) 8(-1.905,2.375)
  silkscreen extent -2.58,-2 2.58,2, body extent -2.57,-3 2.57,3, height 1.75
ICC_TSSOP16_5P1X4P5_P065 [mm]
  rect 1.65x0.4 smd mask+0.05: 1(-2.8,2.275) 2(-2.8,1.625) 3(-2.8,0.975) 4(-2.8,0.325) 5(-2.8,-0.325) 6(-2.8,-0.975) 7(-2.8,-1.625) 8(-2.8,-2.275) 9(2.8,-2.275) 10(2.8,-1.625) 11(2.8,-0.975) 12(2.8,-0.325) 13(2.8,0.325) 14(2.8,0.975) 15(2.8,1.625) 16(2.8,2.275)
  silkscreen extent -2,-2.55 2,2.55, body extent -3.2,-2.55 3.2,2.55, height 1.2
ICC_V-PDFN-8_8X6_P127 [mm]
  rect 1.35x0.8 smd mask+0.05: 1(-3.575,1.905) 2(-3.575,0.635) 3(-3.575,-0.635) 4(-3.575,-1.905) 5(3.575,-1.905) 6(3.575,-0.635) 7(3.575,0.635) 8(3.575,1.905)
  rect 5.4x5.2 smd mask+0.05: 9(0,0)
  silkscreen extent -4,-3 4,3, body extent -4.03,-3 4.02,3, height 1.01
ICC_W-CSP-BGA72_4P511X4P023_P050 [mm]
  round 0.25 smd mask+0.05: A1(-2,1.75) A2(-1.5,1.75) A3(-1,1.75) A4(-0.5,1.75) A5(0,1.75) A6(0.5,1.75) A7(1,1.75) A8(1.5,1.75) A9(2,1.75) B1(-2,1.25) B2(-1.5,1.25) B3(-1,1.25) B4(-0.5,1.25) B5(0,1.25) B6(0.5,1.25) B7(1,1.25) B8(1.5,1.25) B9(2,1.25) C1(-2,0.75) C2(-1.5,0.75) C3(-1,0.75) C4(-0.5,0.75) C5(0,0.75) C6(0.5,0.75) C7(1,0.75) C8(1.5,0.75) C9(2,0.75) D1(-2,0.25) D2(-1.5,0.25) D3(-1,0.25) D4(-0.5,0.25) D5(0,0.25) D6(0.5,0.25) D7(1,0.25) D8(1.5,0.25) D9(2,0.25) E1(-2,-0.25) E2(-1.5,-0.25) E3(-1,-0.25) E4(-0.5,-0.25) E5(0,-0.25) E6(0.5,-0.25) E7(1,-0.25) E8(1.5,-0.25) E9(2,-0.25) F1(-2,-0.75) F2(-1.5,-0.75) F3(-1,-0.75) F4(-0.5,-0.75) F5(0,-0.75) F6(0.5,-0.75) F7(1,-0.75) F8(1.5,-0.75) F9(2,-0.75) G1(-2,-1.25) G2(-1.5,-1.25) G3(-1,-1.25) G4(-0.5,-1.25) G5(0,-1.25) G6(0.5,-1.25) G7(1,-1.25) G8(1.5,-1.25) G9(2,-1.25) H1(-2,-1.75) H2(-1.5,-1.75) H3(-1,-1.75) H4(-0.5,-1.75) H5(0,-1.75) H6(0.5,-1.75) H7(1,-1.75) H8(1.5,-1.75) H9(2,-1.75)
  silkscreen extent -2.42,-2.03 2.28,2.17, body extent -2.28,-2.04 2.28,2.04, height 0.78
L0603 [mm]
  rect 0.8x0.95 smd mask+0.05: 1(-0.8,0) 2(0.8,0)
  silkscreen extent -1.33,-0.6 1.33,0.6, body extent -0.87,-0.47 0.87,0.47, height 0.95
L1210_LQH [mm]
  rect 1.7x3.1 smd mask+0.05: 1(-1.1,0) 2(1.1,0)
  silkscreen extent -2.05,-1.65 2.05,1.65, body extent -1.75,-1.36 1.75,1.36, height 2
LCD_DRAWING_PROJET-MB1274 [mm]
  silkscreen extent -29.75,-65.09 6.95,2.75, body extent -29.75,-61.6 6.85,2.65, height 3
LED_0603_GREEN [mm]
  rect 0.8x0.8 smd mask+0.05: 1(-0.75,0) 2(0.75,0)
  silkscreen extent -0.25,-0.4 1.25,0.4, body extent -0.8,-0.4 0.8,0.4, height 0.6
LED_0603_RED [mm]
  rect 0.8x0.8 smd mask+0.05: 1(-0.75,0) 2(0.75,0)
  silkscreen extent -0.25,-0.4 1.25,0.4, body extent -0.8,-0.4 0.8,0.4, height 0.6
LED_BI-GR_HSMF-A201-A00J1 [mm]
  rect 1.1x1.5 smd mask+0.05: 1(-0.75,-1.5) 2(-0.75,1.5) 3(0.75,1.5) 4(0.75,-1.5)
  silkscreen extent -1.65,-1.85 1.65,1.85, body extent -1.5,-1.85 1.5,1.85, height 2.1
MIC_HCLGA_3X4X1_4LD [mm]
  rect 0.4x0.95 smd paste+0 mask+0.05: 1(0.45,-0.675) 2(0.45,0.675) 3(-0.45,0.675) 4(-0.45,-0.675)
  rect 1.3x0.35 smd paste+0 mask+0.05: 5(0,-1.725) 6(0,1.725)
  rect 0.35x2.3 smd paste+0 mask+0.05: 7(1.225,0) 8(-1.225,0)
  silkscreen extent -1.55,-2.05 1.55,2.05, body extent -1.45,-1.95 1.45,1.95, height 1
MIC_STM_MP23DB01MMTR [mm]
  rect 0.725x0.522 smd mask+0.05: 1(-0.838,1.364) 2(-0.838,0.542) 4(0.838,0.542) 5(0.838,1.364)
  round 0.2 smd mask+0.05: 3(0,-1.373)
  round 0 hole 0.325 unplated mask+0.05: 6(0,-0.71)
  Top Layer circle w0.3: c0,-0.71 r0.663
  silkscreen extent -1.33,-1.75 1.33,1.75, body extent -1.33,-1.76 1.33,1.75, height 5
MIRE_PLACE_SMD_0P8MM [mm]
  round 0.8 smd mask+0.2: 1(0,0)
  Top Layer keep-out circle w0.01: c0,0 r0.804
MOD_WIFI_INVENTEK-SYSTEMS_ISM43362-M3G-L44-E-SPI-CXX [mm] "INTEGRATED ANTENNA"
  rect 0.84x0.84 smd mask+0.05: 1(4.11,6.88) 2(2.653,6.88) 3(1.196,6.88) 4(-0.261,6.88) 5(-1.718,6.88) 6(-3.175,6.88) 7(-4.632,6.88) 8(-6.089,6.88) 9(-7.546,6.88) 10(-9.003,6.88) 11(-10.46,6.88) 12(-11.917,6.88) 13(-13.374,6.88) 14(-14.574,5.68) 15(-14.574,4.26) 16(-14.574,2.84) 17(-14.574,1.42) 18(-14.574,0) 19(-14.574,-1.42) 20(-14.574,-2.84) 21(-14.574,-4.26) 22(-14.574,-5.68) 23(-13.374,-6.88) 24(-11.917,-6.88) 25(-10.46,-6.88) 26(-9.003,-6.88) 27(-7.546,-6.88) 28(-6.089,-6.88) 29(-4.632,-6.88) 30(-3.175,-6.88) 31(-1.718,-6.88) 32(-0.261,-6.88) 33(1.196,-6.88) 34(2.653,-6.88) 35(4.11,-6.88) 36(5.31,-5.68) 37(5.31,-4.26) 38(5.31,-2.84) 39(5.31,-1.42) 40(5.31,0) 41(5.31,1.42) 42(5.31,2.84) 43(5.31,4.26) 44(5.31,5.68)
  silkscreen extent -15,-7.25 15,7.25, body extent -15,-7.25 15,7.25, height 2.9
MOS_SOT23-5L [mm]
  rect 0.6x1.3 smd mask+0.05: 1(-0.95,-1.1) 2(0,-1.1) 3(0.95,-1.1) 4(0.95,1.1) 5(-0.95,1.1)
  silkscreen extent -1.6,-0.95 1.6,0.97, body extent -1.52,-1.25 1.52,1.25, height 1.45
NPN_SOT23 [mm]
  rect 1x1.4 smd mask+0.05: 1(-0.95,-1.1) 2(0.95,-1.1) 3(0,1.1)
  silkscreen extent -1.63,-0.82 1.63,0.82, body extent -1.56,-1.25 1.56,1.25, height 1.1
PTH_M1261-3005-N_3P5X6_M3_H14#1 [mm]
  round 6 hole 3.5 mask+0.05: 1(0,0)
  silkscreen extent -3.25,-3.25 3.25,3.25, body extent -2.5,-2.5 2.5,2.5, height 14
PTH_M1261-3005-N_3P5X6_M3_H14#2 [mm]
  round 1 hole 3.5 unplated mask+0.05: 1(0,0)
  silkscreen extent -3.25,-3.25 3.25,3.25, body extent -2.5,-2.5 2.5,2.5, height 14
R0402 [mm]
  rect 0.51x0.7 smd mask+0.05: 1(-0.45,0) 2(0.45,0)
  silkscreen extent -0.72,-0.43 0.72,0.43, body extent -0.52,-0.3 0.52,0.3, height 0.4
R0603 [mm]
  rect 0.64x1 smd mask+0.05: 1(-0.7,0) 2(0.7,0)
  silkscreen extent -1.05,-0.58 1.05,0.58, body extent -0.9,-0.5 0.9,0.5, height 0.56
REG_SOT23-5L [mm]
  rect 0.6x1.3 smd mask+0.05: 1(-0.95,-1.1) 2(0,-1.1) 3(0.95,-1.1) 4(0.95,1.1) 5(-0.95,1.1)
  silkscreen extent -1.6,-0.95 1.6,0.97, body extent -1.52,-1.25 1.52,1.25, height 1.1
